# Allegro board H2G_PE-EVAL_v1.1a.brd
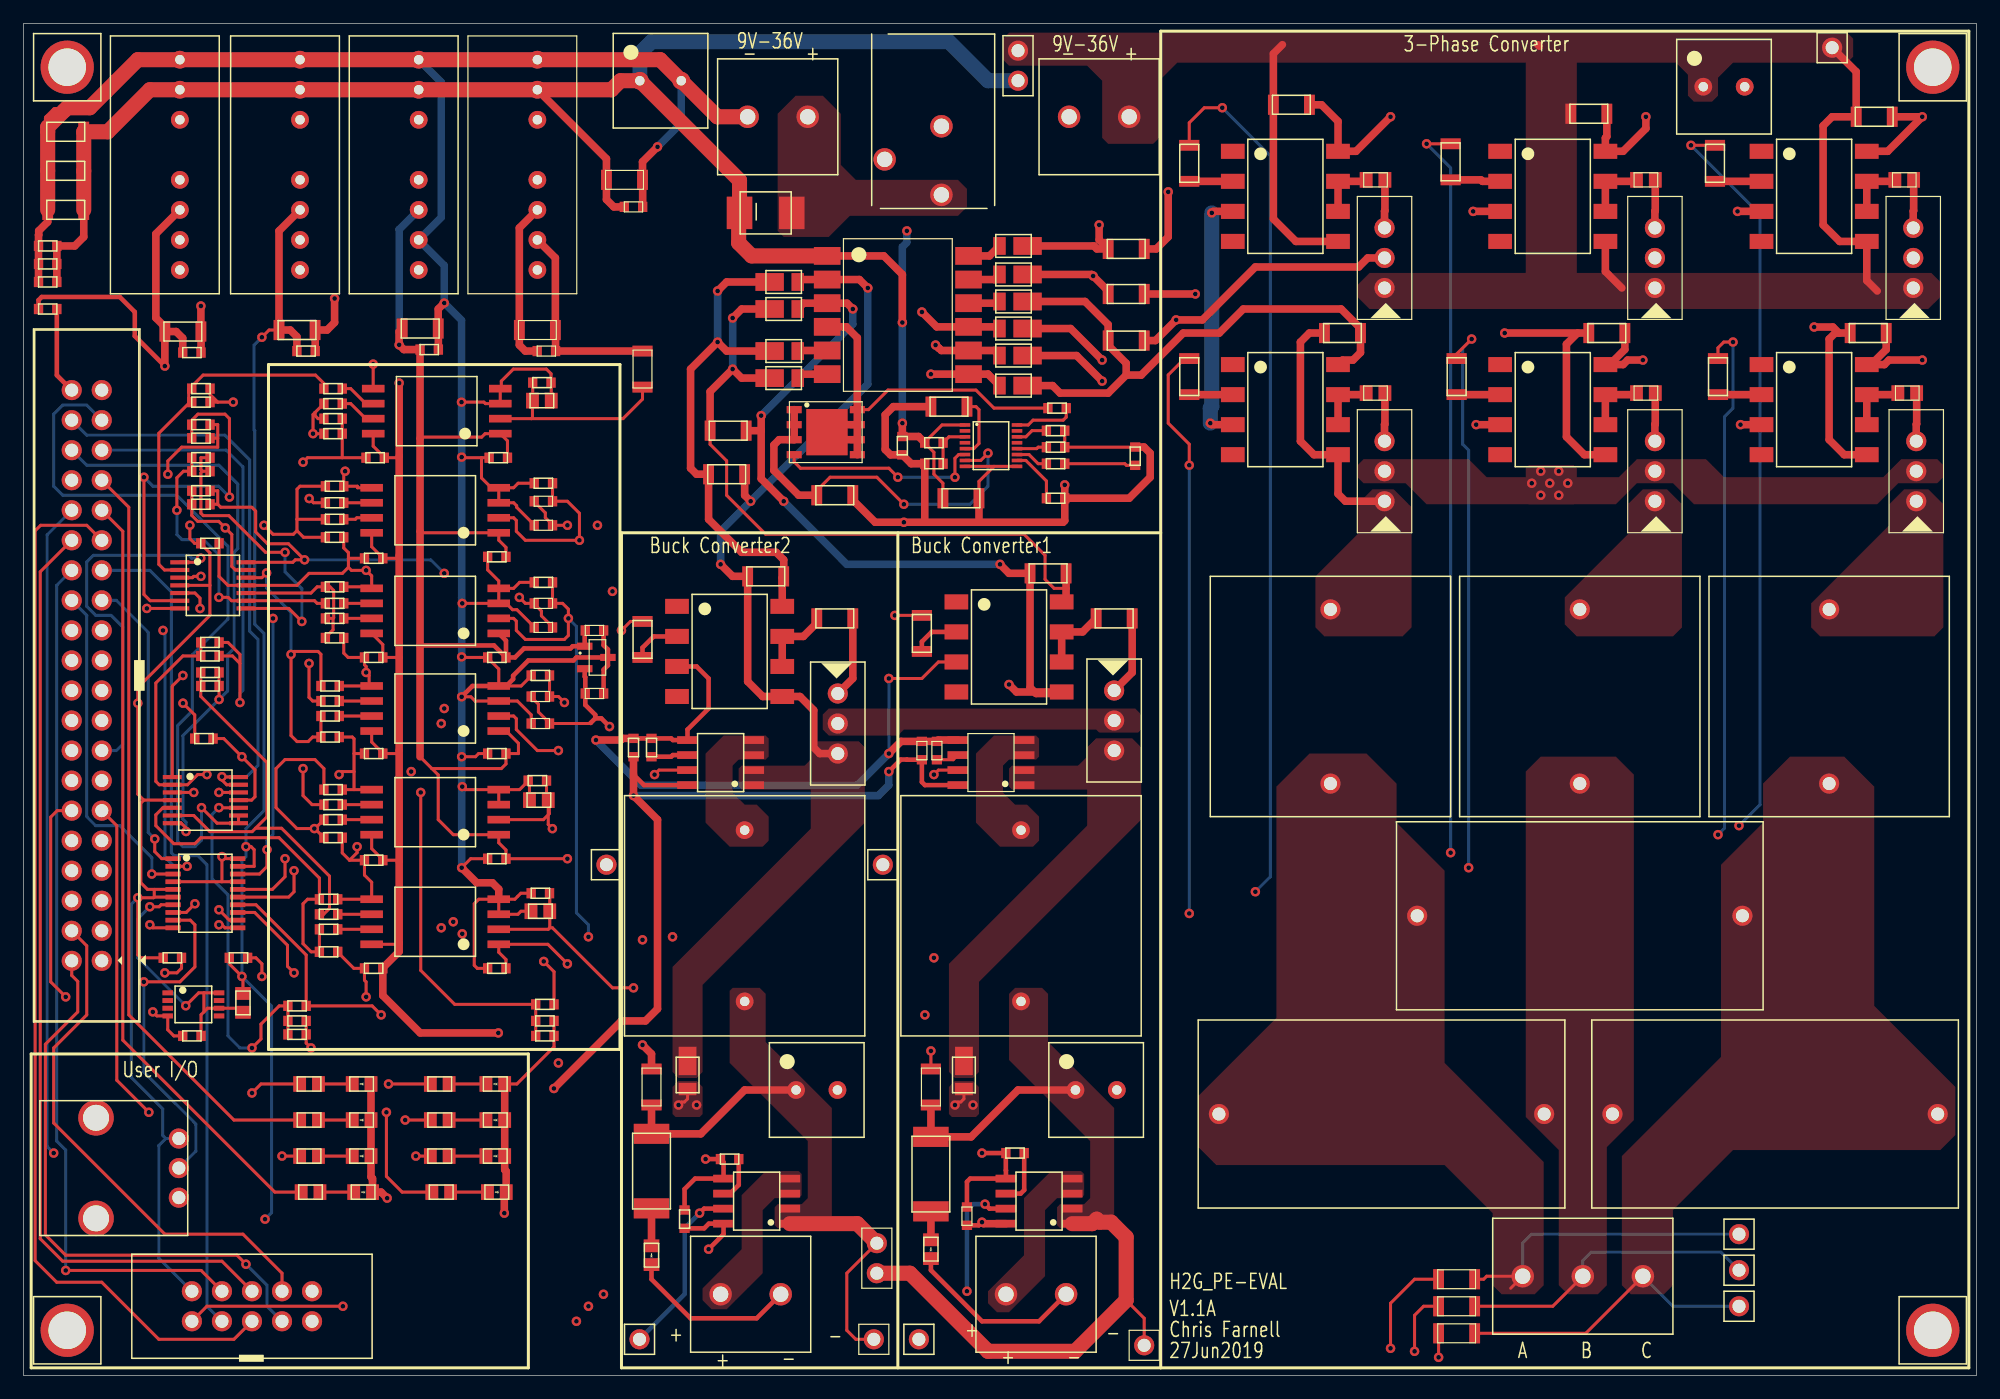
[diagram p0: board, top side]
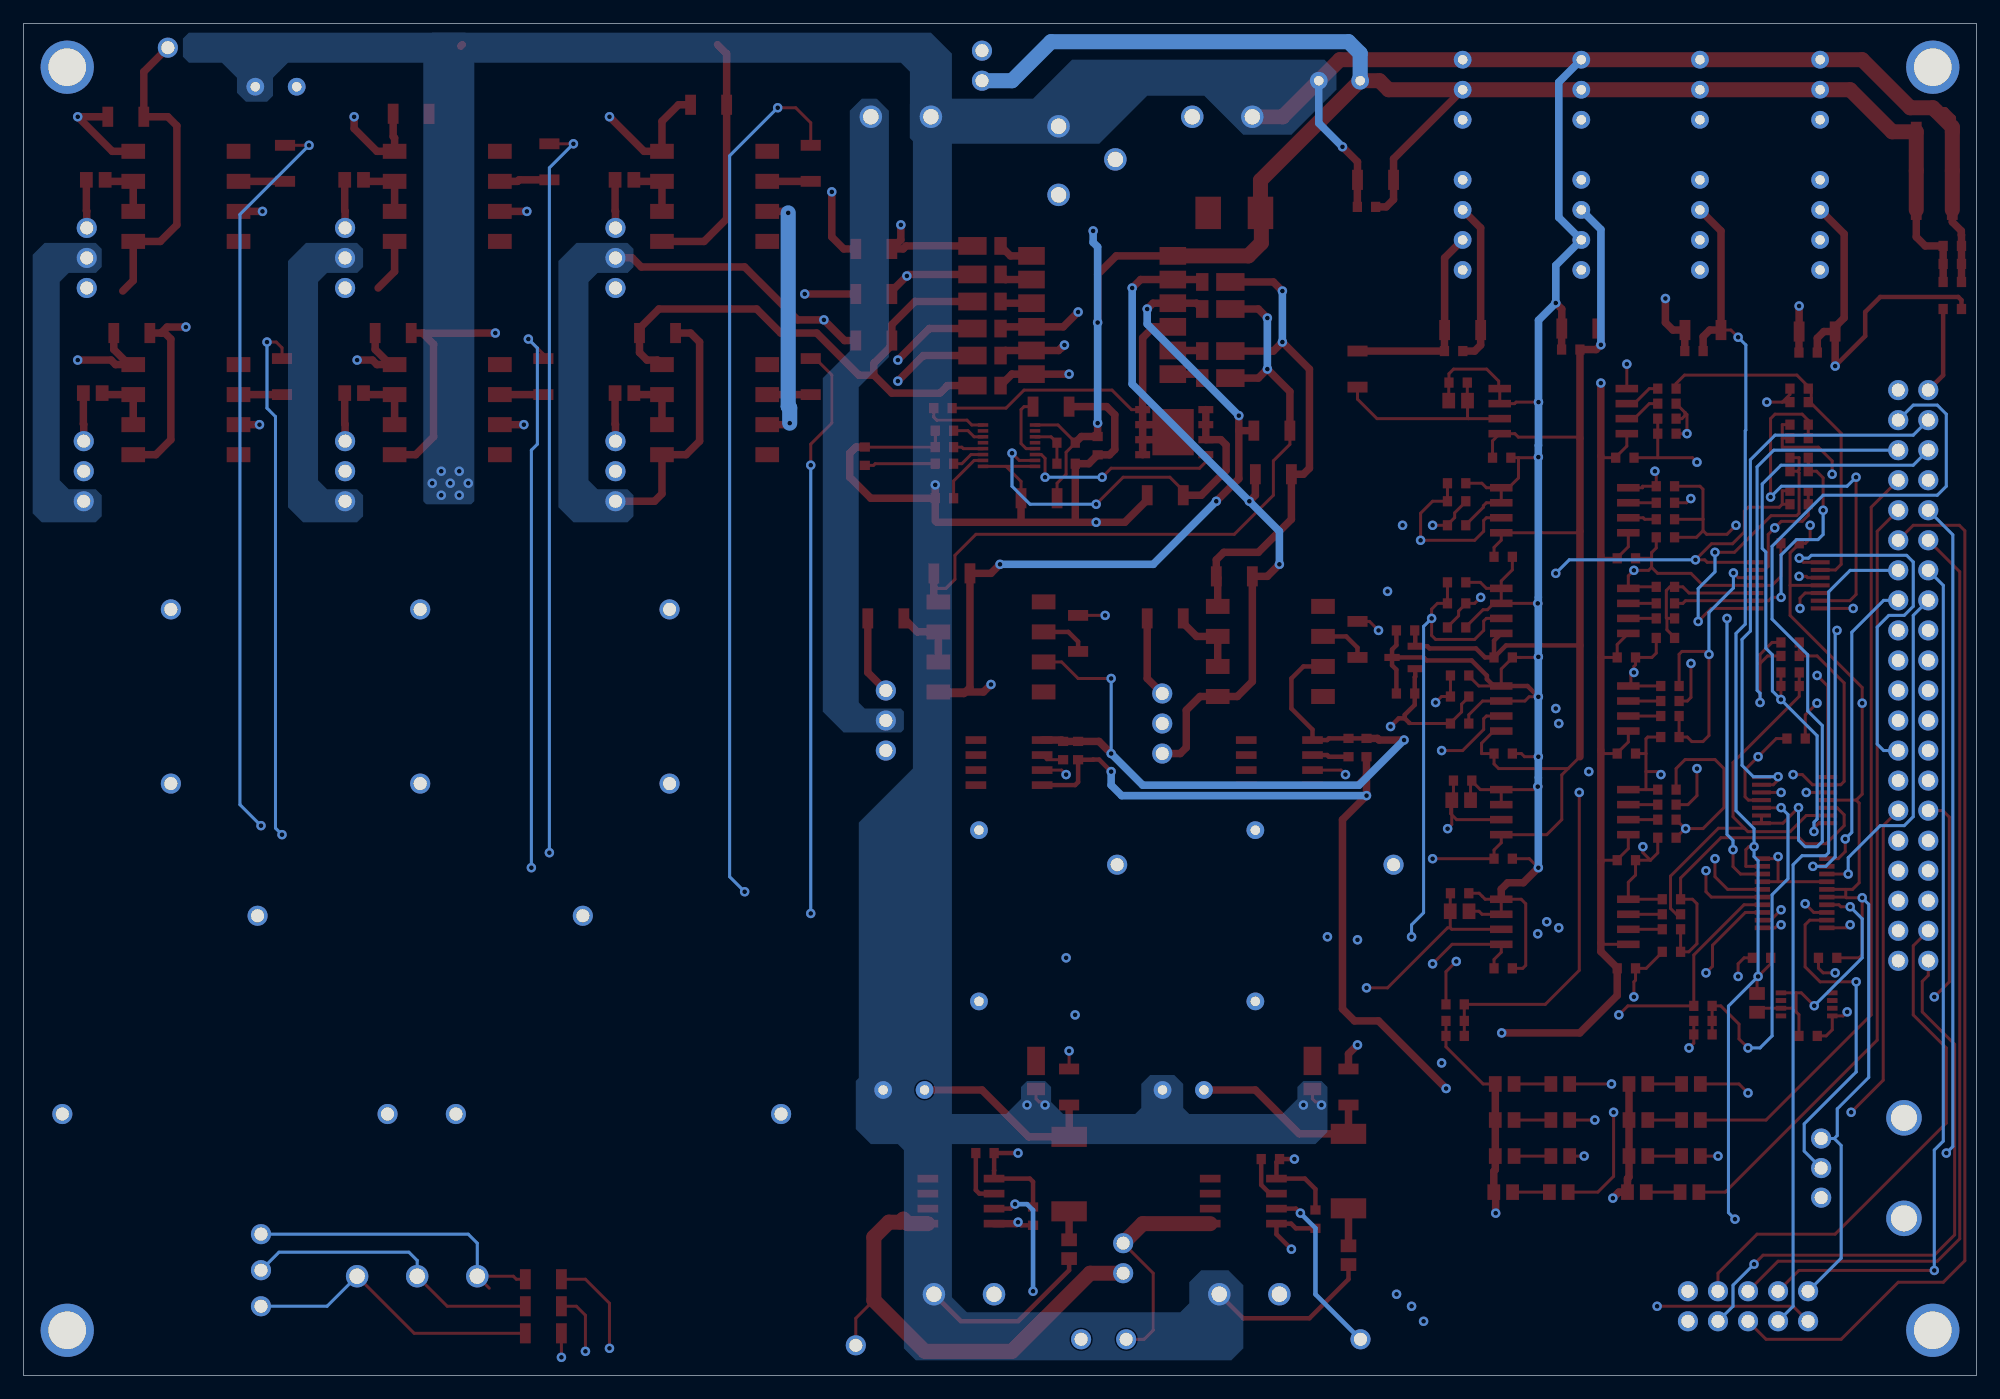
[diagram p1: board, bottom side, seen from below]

Outline 165.1 x 114.3 mm; copper layers: TOP, LAYER2, LAYER3, BOTTOM. Coordinates in mm from the lower left corner of the outline.
Outline path: 0,114.3 165.1,114.3 165.1,0 0,0 0,114.3

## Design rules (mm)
constraint set DEFAULT: min track width 0.254

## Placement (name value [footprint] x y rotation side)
ADC1  AD7928BRUZ  [20-TSSOP]  15.37 40.77 0 top
C1  10uF  [ECQ-E2106KFB]  114.81 22.1 0 top
C2  10uF  [ECQ-E2106KFB]  148.08 22.1 0 top
C3  10uF  [ECQ-E2106KFB]  131.57 38.86 0 top
C4  100uF  [UVZ1H101MPD]  90.68 24.13 0 top
C5  100uF  [UVZ1H101MPD]  53.85 109.47 0 top
C16  10uF  [C_1206]  79.25 74.17 0 top
C17  1uF  [C_0603]  74.29 78.61 270 top
C18  4.7uF  [C_1206]  78.23 81.92 180 top
C19  2.2nF  [C_0603]  87.25 74.17 180 top
C20  4.7nF  [C_0603]  93.98 77.72 270 top
C21  10uF  [C_1206]  93.22 87.5 0 top
C22  10uF  [C_1206]  93.22 91.44 0 top
C23  10uF  [C_1206]  93.22 95.25 0 top
C24  10uF  [C_1206]  59.56 79.88 0 top
C25  10uF  [C_1206]  59.44 76.2 0 top
C26  10uF  [C_1206]  3.56 105.16 180 top
C27  10uF  [C_1206]  3.56 101.85 180 top
C28  10uF  [C_1206]  13.46 88.27 0 top
C29  10uF  [C_1206]  23.11 88.39 0 top
C30  1uF  [C_0603]  2.03 95.5 180 top
C31  1uF  [C_0603]  2.03 93.98 180 top
C32  1uF  [C_0603]  23.88 86.61 0 top
C33  1uF  [C_0603]  14.22 86.49 0 top
C34  100uF  [UVZ1H101MPD]  143.76 108.97 0 top
C35  100uF  [UVZ1H101MPD]  67.06 24.13 0 top
C36  4.7uF  [C_1206]  107.19 107.44 180 top
C37  4.7uF  [C_1206]  132.33 106.68 180 top
C38  4.7uF  [C_1206]  156.46 106.43 180 top
C39  4.7uF  [C_1206]  86.61 67.82 180 top
C40  4.7uF  [C_1206]  111.51 88.14 180 top
C41  4.7uF  [C_1206]  133.86 88.14 180 top
C42  4.7uF  [C_1206]  155.96 88.14 180 top
C43  4.7uF  [C_1206]  62.74 67.56 180 top
C50  1nF  [C_0603]  83.82 18.8 180 top
C51  1nF  [C_0603]  59.69 18.29 180 top
C52  0.1uF  [C_0603]  79.76 13.46 90 top
C53  0.1uF  [C_0603]  55.88 13.21 90 top
C54  10uF  [C_1206]  3.56 98.55 180 top
C55  10uF  [C_1206]  33.53 88.52 0 top
C56  1uF  [C_0603]  2.03 92.46 180 top
C57  1uF  [C_0603]  34.29 86.74 0 top
C58  100pF  [C_0603]  43.81 83.95 0 top
C59  0.1uF  [C_0603]  40.13 77.6 180 top
C60  0.1uF  [C_0603]  29.72 77.6 180 top
C61  100pF  [C_0603]  14.99 82.3 0 top
C62  100pF  [C_0603]  26.16 79.63 180 top
C63  100pF  [C_0603]  43.94 75.44 180 top
C64  0.1uF  [C_0603]  40 69.22 180 top
C65  0.1uF  [C_0603]  29.59 69.09 180 top
C66  100pF  [C_0603]  14.99 79.25 0 top
C67  100pF  [C_0603]  26.29 70.87 180 top
C68  100pF  [C_0603]  43.94 67.06 180 top
C69  0.1uF  [C_0603]  40 60.71 180 top
C70  0.1uF  [C_0603]  29.59 60.71 180 top
C71  100pF  [C_0603]  14.99 76.45 0 top
C72  100pF  [C_0603]  26.29 62.36 180 top
C73  100pF  [C_0603]  43.69 59.18 180 top
C74  0.1uF  [C_0603]  40 52.58 180 top
C75  0.1uF  [C_0603]  29.59 52.58 180 top
C76  100pF  [C_0603]  14.99 73.66 0 top
C77  100pF  [C_0603]  25.91 53.98 180 top
C78  100pF  [C_0603]  43.43 50.29 180 top
C79  0.1uF  [C_0603]  40 43.69 180 top
C80  0.1uF  [C_0603]  29.59 43.56 180 top
C81  100pF  [C_0603]  15.75 60.83 0 top
C82  100pF  [C_0603]  26.16 45.47 180 top
C83  100pF  [C_0603]  43.69 40.77 180 top
C84  0.1uF  [C_0603]  40 34.42 180 top
C85  0.1uF  [C_0603]  29.59 34.42 180 top
C86  100pF  [C_0603]  15.75 58.29 0 top
C87  100pF  [C_0603]  25.78 35.81 180 top
C88  220pF  [C_0603]  23.11 28.83 0 top
C89  220pF  [C_0603]  44.07 28.7 0 top
C96  1uF  [C_0603]  12.57 35.31 0 top
C97  1uF  [C_0603]  18.16 35.31 0 top
C98  1uF  [C_0603]  15.75 70.36 0 top
C99  1uF  [C_0603]  15.24 53.85 0 top
C100  0.1uF  [C_0603]  2.03 90.17 0 top
C102  1uF  [C_0603]  14.22 28.7 0 top
C105  1nF  [C_0603]  53.09 53.09 90 top
C106  0.1uF  [C_0603]  51.56 53.09 90 top
C108  1nF  [C_0603]  77.22 52.83 90 top
C109  0.1uF  [C_0603]  75.95 52.83 90 top
C110  10uF  [C_1206]  43.43 88.39 0 top
C111  1uF  [C_0603]  44.2 86.61 0 top
C112  10uF  [C_1206]  50.8 101.09 0 top
C113  1uF  [C_0603]  51.56 98.81 0 top
C114  0.1uF  [C_0603]  48.26 57.66 0 top
C115  0.1uF  [C_0603]  48.26 62.99 0 top
C116  0.1uF  [C_0603]  43.94 71.88 180 top
C117  0.1uF  [C_0603]  43.94 63.25 180 top
C118  0.1uF  [C_0603]  43.69 55.12 180 top
D1  STPS3150U  [DO-214AA_SMB]  62.74 98.3 0 top
D5  DFLS260-7  [POWERDI-123]  83.69 90.81 180 top
D6  DFLS260-7  [POWERDI-123]  83.69 93.09 180 top
D7  DFLS260-7  [POWERDI-123]  83.69 95.5 180 top
D8  DFLS260-7  [POWERDI-123]  64.26 84.33 0 top
D9  DFLS260-7  [POWERDI-123]  64.26 86.61 0 top
D10  DFLZ18-7  [POWERDI-123]  83.69 83.69 180 top
D11  DFLZ18-7  [POWERDI-123]  83.69 86.23 180 top
D12  DFLZ18-7  [POWERDI-123]  83.69 88.52 180 top
D13  DFLZ18-7  [POWERDI-123]  64.26 90.17 0 top
D14  DFLZ18-7  [POWERDI-123]  64.26 92.46 0 top
D15  DFLS260-7  [POWERDI-123]  79.5 25.4 270 top
D16  DFLS260-7  [POWERDI-123]  56.13 25.4 270 top
D17  LED-R  [LED_0805-RED]  76.71 10.67 90 top
D18  LED-G  [LED_0805-GREEN]  53.09 10.16 90 top
D19  LED-G  [LED_0805-GREEN]  40 15.49 180 top
D20  LED-Y  [LED_0805-YELLOW]  39.88 18.54 180 top
D21  LED-O  [LED_0805-ORANGE]  39.88 21.59 180 top
D22  LED-R  [LED_0805-RED]  39.88 24.64 180 top
D23  LED-G  [LED_0805-GREEN]  28.7 15.49 180 top
D24  LED-Y  [LED_0805-YELLOW]  28.57 18.54 180 top
D25  LED-O  [LED_0805-ORANGE]  28.57 21.59 180 top
D26  LED-R  [LED_0805-RED]  28.57 24.64 180 top
J1  AWHW 40G-0202-T  [40-IDC-M]  5.33 59.18 180 top
J2  -  [1715721]  63.75 106.43 270 top
J3  -  [1715734]  131.83 8.38 90 top
J4  -  [1715721]  85.6 6.86 90 top
J5  -  [1715721]  61.47 6.86 90 top
J6  PJ-102BH  [DC-PWR_JACK]  77.6 106.17 0 top
J7  AWHW 10G-0202-T  [10-IDC-M]  19.3 5.84 90 top
J8  -  [1715721]  90.93 106.43 270 top
JP1  -  [J_1X2]  84.07 110.74 180 top
JP5  -  [J_1X2]  72.14 9.91 180 top
L1  180uH  [PCV-2-184-05L]  110.49 57.4 270 top
L2  180uH  [PCV-2-184-05L]  131.57 57.4 270 top
L3  180uH  [PCV-2-184-05L]  152.65 57.4 270 top
L4  560uH  [PCV-2-564-02L]  84.33 38.86 270 top
L5  560uH  [PCV-2-564-02L]  60.96 38.86 270 top
MECH1  Mech_Hole  [4-40_SCREW]  3.68 110.62 0 top
MECH2  Mech_Hole  [4-40_SCREW]  3.68 3.81 0 top
MECH3  Mech_Hole  [4-40_SCREW]  161.42 110.62 0 top
MECH4  Mech_Hole  [4-40_SCREW]  161.42 3.81 0 top
PM1  EC4SAW-24S33N  [SIP-8]  22.1 102.36 0 top
PM2  EC4SAW-24S05N  [SIP-8]  11.94 102.36 0 top
PM3  EC4SAW-24S05N  [SIP-8]  32.13 102.36 0 top
PM4  EC4SAW-24S15N  [SIP-8]  42.16 102.36 0 top
Q1  STGP15H60DF  [TO-220]  92.2 55.37 0 top
Q2  STGP15H60DF  [TO-220]  68.83 55.12 0 top
Q3  Si7898DP  [SO-8_PP]  67.82 79.76 0 top
R8  825k  [R_0603]  76.96 78.87 0 top
R9  215k  [R_0603]  76.96 77.09 0 top
R10  133k  [R_0603]  87.25 78.49 180 top
R11  10k  [R_0603]  87.25 77.09 180 top
R12  71.5k  [R_0603]  87.38 81.79 180 top
R13  6.04k  [R_0603]  87.25 79.88 0 top
R14  0.01  [R_1206]  68.58 74.42 180 top
R15  2.49k  [R_2512]  76.71 17.02 270 top
R16  2.49k  [R_2512]  53.09 17.27 270 top
R17  120  [R_1206]  98.55 102.49 270 top
R19  120  [R_1206]  120.65 102.62 270 top
R21  120  [R_1206]  143 102.49 270 top
R23  120  [R_1206]  75.95 62.74 270 top
R24  10  [R_1206]  92.2 64.01 0 top
R25  120  [R_1206]  98.55 84.46 270 top
R27  120  [R_1206]  121.16 84.46 270 top
R29  120  [R_1206]  143.26 84.46 270 top
R31  120  [R_1206]  52.32 62.23 270 top
R32  10  [R_1206]  68.58 64.01 0 top
R33  1Meg  [R_1206]  52.32 85.09 270 top
R35  10k  [R_0603]  26.16 82.17 180 top
R36  10k  [R_0603]  26.16 83.44 180 top
R37  10k  [R_0603]  26.16 80.9 180 top
R38  10k  [R_0603]  14.99 83.44 0 top
R39  31.6k  [R_0805]  43.81 82.42 0 top
R40  1Meg  [R_1206]  121.16 8.13 180 top
R41  10k  [R_0603]  26.29 72.39 180 top
R42  10k  [R_0603]  26.29 73.79 180 top
R43  10k  [R_0603]  26.29 75.18 180 top
R44  10k  [R_0603]  14.99 80.39 0 top
R45  13.7k  [R_0603]  43.94 73.91 180 top
R46  1Meg  [R_1206]  121.16 5.84 180 top
R47  10k  [R_0603]  26.29 64.01 180 top
R48  10k  [R_0603]  26.29 65.28 180 top
R49  10k  [R_0603]  26.29 66.68 180 top
R50  10k  [R_0603]  14.99 77.6 0 top
R51  13.7k  [R_0603]  43.94 65.28 180 top
R52  1Meg  [R_1206]  121.16 3.56 180 top
R53  10k  [R_0603]  25.91 55.75 180 top
R54  10k  [R_0603]  25.91 57.02 180 top
R55  10k  [R_0603]  25.91 58.29 180 top
R56  10k  [R_0603]  14.99 74.8 0 top
R57  13.7k  [R_0603]  43.69 57.4 180 top
R58  1Meg  [R_1206]  76.71 24.38 90 top
R59  10k  [R_0603]  26.16 46.99 180 top
R60  10k  [R_0603]  26.16 48.26 180 top
R61  10k  [R_0603]  26.16 49.53 180 top
R62  10k  [R_0603]  15.75 61.98 0 top
R63  31.6k  [R_0805]  43.56 48.64 180 top
R64  1Meg  [R_1206]  53.09 24.38 90 top
R65  10k  [R_0603]  25.78 37.72 180 top
R66  10k  [R_0603]  25.78 38.99 180 top
R67  10k  [R_0603]  25.78 40.26 180 top
R68  10k  [R_0603]  15.75 59.44 0 top
R69  31.6k  [R_0805]  43.69 39.24 180 top
R70  10k  [R_0603]  23.11 31.24 180 top
R71  15k  [R_0603]  23.11 29.97 0 top
R72  10k  [R_0603]  44.07 31.37 180 top
R73  15k  [R_0603]  44.07 29.97 0 top
R74  PTV09A-4020F-B103  [9MM_POT]  7.62 17.53 180 top
R75  1k  [R_0805]  18.54 31.5 270 top
R80  220  [R_0805]  35.31 15.49 0 top
R81  220  [R_0805]  35.18 18.54 0 top
R82  220  [R_0805]  35.18 21.59 0 top
R83  220  [R_0805]  35.18 24.64 0 top
R84  220  [R_0805]  24.26 15.49 0 top
R85  220  [R_0805]  24.13 18.54 0 top
R86  220  [R_0805]  24.13 21.59 0 top
R87  220  [R_0805]  24.13 24.64 0 top
R88  1k  [R_0805]  114.3 101.09 0 top
R89  1k  [R_0805]  114.3 83.06 0 top
R90  1k  [R_0805]  137.16 101.09 0 top
R91  1k  [R_0805]  137.16 83.06 0 top
R92  1k  [R_0805]  159 101.09 0 top
R93  1k  [R_0805]  159.26 83.06 0 top
SCR1  SJ6020LTP  [TO-220]  115.06 94.49 180 top
SCR2  SJ6020LTP  [TO-220]  115.06 76.45 180 top
SCR3  SJ6020LTP  [TO-220]  137.92 94.49 180 top
SCR4  SJ6020LTP  [TO-220]  137.92 76.45 180 top
SCR5  SJ6020LTP  [TO-220]  159.77 94.49 180 top
SCR6  SJ6020LTP  [TO-220]  160.02 76.45 180 top
TP1  TP-Y  [TP-YELLOW]  75.69 3.05 0 top
TP2  TP-Y  [TP-YELLOW]  52.07 3.05 0 top
TP3  TP-Y  [TP-YELLOW]  72.64 43.18 0 top
TP4  TP-Y  [TP-YELLOW]  49.28 43.18 0 top
TP5  TP-Y  [TP-YELLOW]  145.03 11.94 0 top
TP6  TP-Y  [TP-YELLOW]  145.03 8.89 0 top
TP7  TP-Y  [TP-YELLOW]  145.03 5.84 270 top
TP8  TP-Y  [TP-YELLOW]  152.91 112.27 270 top
TP9  TP-Y  [TP-YELLOW]  94.74 2.54 0 top
TP10  TP-Y  [TP-YELLOW]  71.88 3.05 0 top
TX1  VP1-0102-R  [TX-VP1]  73.91 89.66 0 top
U3  LT3748EMS#PBF-ND  [16-MSOP]  81.79 78.61 0 top
U6  ACS714LLCTR-05B-T  [8-SOIC]  85.85 14.73 180 top
U7  ACS714LLCTR-05B-T  [8-SOIC]  61.98 14.73 180 top
U8  HCPL-3120-300E  [8-DIP_GW]  106.68 99.69 0 top
U9  HCPL-3120-300E  [8-DIP_GW]  129.29 99.69 0 top
U10  HCPL-3120-300E  [8-DIP_GW]  151.38 99.69 0 top
U11  HCPL-3120-300E  [8-DIP_GW]  83.31 61.59 0 top
U12  HCPL-3120-300E  [8-DIP_GW]  106.68 81.66 0 top
U13  HCPL-3120-300E  [8-DIP_GW]  129.29 81.66 0 top
U14  HCPL-3120-300E  [8-DIP_GW]  151.38 81.66 0 top
U15  HCPL-3120-300E  [8-DIP_GW]  59.69 61.21 0 top
U16  OPA4322AIPWR  [OPA4332_14-TSSOP]  16 66.8 0 top
U17  OPA4322AIPWR  [OPA4332_14-TSSOP]  15.37 48.64 0 top
U20  ACPL-C87B  [ACPL-C87X]  34.93 81.53 180 top
U21  ACPL-C87B  [ACPL-C87X]  34.8 73.15 180 top
U22  ACPL-C87B  [ACPL-C87X]  34.8 64.64 180 top
U23  ACPL-C87B  [ACPL-C87X]  34.8 56.39 180 top
U24  ACPL-C87B  [ACPL-C87X]  34.8 47.62 180 top
U25  ACPL-C87B  [ACPL-C87X]  34.8 38.35 180 top
U27  LT1009CZ  [8-MSOP]  14.35 31.37 0 top
U30  ACS714LLCTR-05B-T  [8-SOIC]  58.93 51.82 180 top
U31  ACS714LLCTR-05B-T  [8-SOIC]  81.79 51.82 180 top
U32  ISL21080  [SOT_23-3]  48.51 60.71 0 top

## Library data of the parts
ADC1 = AD7928BRUZ
C1-C3 C16-C33 C36-C43 C50-C89 C96-C100 C102 C105 C106 C108-C118 = CAP NP
C4 C5 C34 C35 = CAP P
D1 D5-D9 D15 D16 = D-Schottky
D10-D14 = D-Zener
D17-D26 = LED
J1 = Header_2x20
J2 J4 J5 J8 = Connector-2
J3 = Connector-3
J6 = DC-Jack_3
J7 = Header_2x5
JP1 JP5 = JP2
L1-L5 = Ind
MECH1-MECH4 = Mech_Hole
PM1-PM4 = EC4SA
Q1 Q2 = IGBT_TO220
Q3 = N-FET_Si7898DP
R8-R17 R19 R21 R23-R25 R27 R29 R31-R33 R35-R73 R75 R80-R93 = R-Standard
R74 = R-POT
SCR1-SCR6 = SJ6020LTP
TP1-TP10 = TP
TX1 = TX_VP1-0102-R
U3 = LT3748EMS#PBF-ND
U6 U7 U30 U31 = ACS714
U8-U15 = HCPL-3120
U16 U17 = OPA4322AIPWR
U20-U25 = ACPL-C87B
U27 = LT1009CZ
U32 = ISL21080

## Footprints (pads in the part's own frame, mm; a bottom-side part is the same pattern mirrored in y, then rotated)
4-40_SCREW
  round 4.5 hole 3.175: 1(0,0)
8-DIP_GW
  rect 2x1.27 smd: 1(-4.45,3.81) 2(-4.45,1.27) 3(-4.45,-1.27) 4(-4.45,-3.81) 5(4.45,-3.81) 6(4.45,-1.27) 7(4.45,1.27) 8(4.45,3.81)
8-MSOP
  rect 0.889x0.42 smd: 1(-2.17,0.975) 2(-2.17,0.325) 3(-2.17,-0.325) 4(-2.17,-0.975) 5(2.17,-0.975) 6(2.17,-0.325) 7(2.17,0.325) 8(2.17,0.975)
8-SOIC
  rect 1.75x0.65 smd: 1(-2.8,1.905) 2(-2.8,0.635) 3(-2.8,-0.635) 4(-2.8,-1.905) 5(2.8,-1.905) 6(2.8,-0.635) 7(2.8,0.635) 8(2.8,1.905)
9MM_POT
  round 3 hole 2.2: (1.5,4.25) (1.5,-4.25)
  round 1.7 hole 1.1: 1(-5.5,2.5) 2(-5.5,0) 3(-5.5,-2.5)
10-IDC-M
  round 1.7 hole 1.1: 1(-1.27,5.08) 2(1.27,5.08) 3(-1.27,2.54) 4(1.27,2.54) 5(-1.27,0) 6(1.27,0) 7(-1.27,-2.54) 8(1.27,-2.54) 9(-1.27,-5.08) 10(1.27,-5.08)
16-MSOP
  rect 0.89x0.305 smd: 1(-2.2,1.75) 2(-2.2,1.25) 3(-2.2,0.75) 4(-2.2,0.25) 5(-2.2,-0.25) 6(-2.2,-0.75) 7(-2.2,-1.25) 8(-2.2,-1.75) 9(2.2,-1.75) 10(2.2,-1.25) 11(2.2,-0.75) 12(2.2,-0.25) 13(2.2,0.25) 14(2.2,0.75) 15(2.2,1.25) 16(2.2,1.75)
20-TSSOP
  rect 1.3x0.4 smd: 1(-2.725,2.925) 2(-2.725,2.275) 3(-2.725,1.625) 4(-2.725,0.975) 5(-2.725,0.325) 6(-2.725,-0.325) 7(-2.725,-0.975) 8(-2.725,-1.625) 9(-2.725,-2.275) 10(-2.725,-2.925) 11(2.725,-2.925) 12(2.725,-2.275) 13(2.725,-1.625) 14(2.725,-0.975) 15(2.725,-0.325) 16(2.725,0.325) 17(2.725,0.975) 18(2.725,1.625) 19(2.725,2.275) 20(2.725,2.925)
40-IDC-M
  round 1.7 hole 1.1: 1(-1.27,24.13) 2(1.27,24.13) 3(-1.27,21.59) 4(1.27,21.59) 5(-1.27,19.05) 6(1.27,19.05) 7(-1.27,16.51) 8(1.27,16.51) 9(-1.27,13.97) 10(1.27,13.97) 11(-1.27,11.43) 12(1.27,11.43) 13(-1.27,8.89) 14(1.27,8.89) 15(-1.27,6.35) 16(1.27,6.35) 17(-1.27,3.81) 18(1.27,3.81) 19(-1.27,1.27) 20(1.27,1.27) 21(-1.27,-1.27) 22(1.27,-1.27) 23(-1.27,-3.81) 24(1.27,-3.81) 25(-1.27,-6.35) 26(1.27,-6.35) 27(-1.27,-8.89) 28(1.27,-8.89) 29(-1.27,-11.43) 30(1.27,-11.43) 31(-1.27,-13.97) 32(1.27,-13.97) 33(-1.27,-16.51) 34(1.27,-16.51) 35(-1.27,-19.05) 36(1.27,-19.05) 37(-1.27,-21.59) 38(1.27,-21.59) 39(-1.27,-24.13) 40(1.27,-24.13)
1715721
  round 1.9 hole 1.3: 1(0,2.54) 2(0,-2.54)
1715734
  round 1.9 hole 1.3: 1(0,5.08) 2(0,0) 3(0,-5.08)
ACPL-C87X
  rect 1.905x0.64 smd: 1(-5.372,1.905) 2(-5.372,0.635) 3(-5.372,-0.635) 4(-5.372,-1.905) 5(5.372,-1.905) 6(5.372,-0.635) 7(5.372,0.635) 8(5.372,1.905)
C_0603
  rect 0.787x0.864 smd: 1(-0.775,0) 2(0.775,0)
C_1206
  rect 0.914x1.702 smd: 1(-1.524,0) 2(1.524,0)
DC-PWR_JACK
  round 1.9 hole 1.3: 1(0,-6.35) 2(0,-0.55) 3(-4.8,-3.35)
DO-214AA_SMB
  rect 2.159x2.743 smd: 1(-2.21,0) 2(2.21,0)
ECQ-E2106KFB
  round 1.7 hole 1.1: 1(-13.75,0) 2(13.75,0)
J_1X2
  round 1.7 hole 1.1: 1(0,1.27) 2(0,-1.27)
LED_0805-GREEN
  rect 1.08x1.321 smd: 1(-0.794,0) 2(0.794,0)
LED_0805-ORANGE
  rect 1.08x1.321 smd: 1(-0.794,0) 2(0.794,0)
LED_0805-RED
  rect 1.08x1.321 smd: 1(-0.794,0) 2(0.794,0)
LED_0805-YELLOW
  rect 1.08x1.321 smd: 1(-0.794,0) 2(0.794,0)
OPA4332_14-TSSOP
  rect 1.6x0.35 smd: 1(-2.8,1.95) 2(-2.8,1.3) 3(-2.8,0.65) 4(-2.8,0) 5(-2.8,-0.65) 6(-2.8,-1.3) 7(-2.8,-1.95) 8(2.8,-1.95) 9(2.8,-1.3) 10(2.8,-0.65) 11(2.8,0) 12(2.8,0.65) 13(2.8,1.3) 14(2.8,1.95)
PCV-2-184-05L
  round 1.7 hole 1.1: 1(-7.365,0) 2(7.365,0)
PCV-2-564-02L
  round 1.5 hole 0.8: 1(-7.24,0) 2(7.24,0)
POWERDI-123
  rect 2.4x1.5 smd: 1(-1.188,0)
  rect 1.05x1.5 smd: 2(1.188,0)
R_0603
  rect 0.787x0.864 smd: 1(-0.775,0) 2(0.775,0)
R_0805
  rect 1.08x1.321 smd: 1(-0.794,0) 2(0.794,0)
R_1206
  rect 0.914x1.702 smd: 1(-1.524,0) 2(1.524,0)
R_2512
  rect 1.7x3 smd: 1(-3.15,0) 2(3.15,0)
SIP-8
  round 1.5 hole 0.8: 1(1.27,8.89) 2(1.27,6.35) 3(1.27,3.81) 5(1.27,-1.27) 6(1.27,-3.81) 7(1.27,-6.35) 8(1.27,-8.89)
SO-8_PP
  rect 1.27x0.61 smd: 1(-2.67,1.905) 2(-2.67,0.635) 3(-2.67,-0.635) 4(-2.67,-1.905) 5(2.67,-1.905) 6(2.67,-0.635) 7(2.67,0.635) 8(2.67,1.905)
  rect 3.5x3.91 smd: 9(0.1,0)
SOT_23-3
  rect 1.3x0.6 smd: 1(-1.075,0.95) 2(-1.075,-0.95) 3(0.889,0)
TO-220
  round 1.7 hole 1.1: 1(0,2.54) 2(0,0) 3(0,-2.54)
TP-YELLOW
  round 1.7 hole 1.1: 1(0,0)
TX-VP1
  rect 2.25x1.5 smd: 1(-5.975,5) 2(-5.975,3) 3(-5.975,1) 4(-5.975,-1) 5(-5.975,-3) 6(-5.975,-5) 7(5.975,-5) 8(5.975,-3) 9(5.975,-1) 10(5.975,1) 11(5.975,3) 12(5.975,5)
UVZ1H101MPD
  round 1.5 hole 0.8: 1(-1.75,0) 2(1.75,0)

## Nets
0V9: C114.1 C116.1 C117.1 C118.1 R45.2 R51.2 R57.2 U32.2(V_OUT)
3V3_ISO: ADC1.19 C29.1 C32.1 C97.1 J7.1 PM1.6 R75.1
5V: C55.1 C57.1 C59.1 C64.1 C69.1 C74.1 C79.1 C84.1 C115.1 PM3.6 U20.1 U21.1 U22.1 U23.1 U24.1 U25.1 U32.1
5V_ISO: ADC1.5 ADC1.6 C28.1 C33.1 C52.1 C53.1 C60.1 C65.1 C70.1 C75.1 C80.1 C85.1 C96.1 C98.1 C99.1 C100.1 C106.1 C109.1 J7.2 PM2.6 R74.3 U6.8 U7.8 U16.4 U17.4 U20.8 U21.8 U22.8 U23.8 U24.8 U25.8 U30.8 U31.8
18V_GU: C36.1 C37.1 C38.1 C110.1 C111.1 PM4.6 U8.8 U9.8 U10.8
18V_IGBT1: C24.1 C39.1 D8.1 D13.1 U11.8
18V_IGBT2: C25.1 C43.1 D9.1 D14.1 U15.8
18V_SCR2: C21.1 C40.1 D5.1 D10.1 U12.8
18V_SCR4: C22.1 C41.1 D6.1 D11.1 U13.8
18V_SCR6: C23.1 C42.1 D7.1 D12.1 U14.8
GND: C4.2 C5.2 C16.2 C17.2 C18.2 C19.1 C20.1 C26.2 C27.2 C30.2 C31.2 C34.2 C35.2 C54.2 C55.2 C56.2 C57.2 C58.2 C59.2 C63.2 C64.2 C68.2 C69.2 C73.2 C74.2 C78.2 C79.2 C83.2 C84.2 C112.2 C113.2 C114.2 C115.2 C116.2 C117.2 C118.2 D15.2 D16.2 D17.1(CATHODE) D18.1(CATHODE) J2.2(P2) J4.2(P2) J5.2(P2) J6.2 J8.2(P2) PM1.1 PM2.1 PM3.1 PM3.7 PM4.1 R9.1 R10.1 R13.2 R14.1 R39.2 R63.2 R69.2 SCR2.2 SCR4.2 SCR6.2 U3.8 U3.9 U20.3 U20.4 U21.3 U21.4 U22.3 U22.4 U23.3 U23.4 U24.3 U24.4 U25.3 U25.4 U32.3
GND_SIGNAL: ADC1.4 ADC1.8 ADC1.17 ADC1.20 C28.2 C29.2 C32.2 C33.2 C50.2 C51.2 C52.2 C53.2 C60.2 C62.1 C65.2 C67.1 C70.2 C72.1 C75.2 C77.1 C80.2 C82.1 C85.2 C87.1 C88.2 C89.2 C96.2 C97.2 C98.2 C99.2 C100.2 C102.1 C105.2 C106.2 C108.2 C109.2 D19.1(CATHODE) D20.1(CATHODE) D21.1(CATHODE) D22.1(CATHODE) D23.1(CATHODE) D24.1(CATHODE) D25.1(CATHODE) D26.1(CATHODE) J1.20 J1.40 J7.9 J7.10 PM1.7 PM2.7 R37.1 R43.1 R49.1 R55.1 R61.1 R67.1 R71.2 R73.2 R74.1 U6.5 U7.5 U8.3 U9.3 U10.3 U11.3 U12.3 U13.3 U14.3 U15.3 U16.11(V-) U17.11(V-) U20.5 U21.5 U22.5 U23.5 U24.5 U25.5 U27.4 U30.5 U31.5
VIN: C5.1 C16.1 C17.1 C26.1 C27.1 C30.1 C31.1 C54.1 C56.1 C112.1 C113.1 D1.1 JP1.1 PM1.2 PM2.2 PM3.2 PM4.2 R8.1 TX1.1 U3.1(VIN)
ADC-VPOT-3V: J1.38 U17.13 U17.14
ADC_DC-LINK: C61.2 J1.15 R38.2 U16.1
ADC_I_BUCK-1_3V: J1.37 U17.8 U17.9
ADC_V_BUCK-1: C81.2 J1.35 R62.2 U17.1
ADC_V_BUCK-2: C86.2 J1.36 R68.2 U17.7
ADC_VA: ADC1.12 C66.2 J1.16 R44.2 U16.7
ADC_VB: ADC1.11 C71.2 J1.17 R50.2 U16.8
ADC_VC: ADC1.10 C76.2 J1.18 R56.2 U16.14
DC-LINK: C34.1 C36.2 C37.2 C38.2 C110.2 C111.2 J8.1 JP1.2 PM4.7 Q1.2 Q2.2 R33.1 SCR1.1(K) SCR3.1(K) SCR5.1(K) TP8.1 U8.5 U9.5 U10.5
DSP_G1: J1.1 R23.1
DSP_G2: J1.2 J7.7
DSP_G3: J1.3 R31.1
DSP_G4: J1.4 J7.8
DSP_G5: J1.5 R17.1
DSP_G6: J1.6 R25.1
DSP_G7: J1.7 R19.1
DSP_G8: J1.8 R27.1
DSP_G9: J1.9 R21.1
DSP_G10: J1.10 R29.1
GPIO-20: J1.27 J7.3
GPIO-21: J1.28 J7.4
GPIO-22: J1.29 J7.5
GPIO-23: J1.30 J7.6
I_BUCK-1: ADC1.14 R70.1 TP1.1 U6.7(VOUT)
I_BUCK-2: ADC1.13 TP2.1 U7.7(VOUT)
I_L4: ADC1.16 TP3.1 U31.7(VOUT)
I_L5: ADC1.15 TP4.1 U30.7(VOUT)
IGBT_G1: Q1.1(G) R24.2
IGBT_G2: Q2.1(G) R32.2
IGBT_S1: C24.2 C39.2 D13.2 D15.1 Q1.3 TX1.3 U11.5 U31.1 U31.2
IGBT_S2: C25.2 C43.2 D14.2 D16.1 Q2.3 TX1.2 U15.5 U30.1 U30.2
LED1: J1.11 R80.1
LED2: J1.12 R81.1
LED3: J1.13 R82.1
LED4: J1.14 R83.1
LED5: J1.31 R84.1
LED6: J1.32 R85.1
LED7: J1.33 R86.1
LED8: J1.34 R87.1
SCR_G1: R88.2 SCR1.3
SCR_G2: R89.2 SCR2.3
SCR_G3: R90.2 SCR3.3
SCR_G4: R91.2 SCR4.3
SCR_G5: R92.2 SCR5.3
SCR_G6: R93.2 SCR6.3
SPI_CS: ADC1.3 J1.26
SPI_DIN: ADC1.2 J1.23
SPI_DOUT: ADC1.18 J1.24
SPI_SCLK: ADC1.1 J1.25
SW_1: J1.21
SW_2: J1.22
V_BUCK-1: C4.1 JP5.1 L4.2 R15.1 R58.1 TP9.1 U6.1 U6.2
V_BUCK-2: C35.1 JP5.2 L5.2 R16.1 R64.1 TP10.1 U7.1 U7.2
VA: C1.1 C3.1 J3.1 L1.2 R40.1 TP5.1
VB: C1.2 C2.1 J3.2 L2.2 R46.1 TP6.1
VC: C2.2 C3.2 J3.3(P3) L3.2 R52.1 TP7.1
VMID1: C21.2 C40.2 D10.2 L1.1 SCR1.2 SCR2.1(K) TX1.7 U12.5
VMID2: C22.2 C41.2 D11.2 L2.1 SCR3.2 SCR4.1(K) TX1.8 U13.5
VMID3: C23.2 C42.2 D12.2 L3.1 SCR5.2 SCR6.1(K) TX1.9 U14.5
VPOT: ADC1.9(VIN7) R72.1 R74.2(WIPER)
N07970: R8.2 R9.2 U3.3
N08403: C18.1 U3.5
N08410: R10.2 U3.12
N08443: C19.2 U3.10
N08455: R11.2 U3.11
N08467: C20.2 R11.1
N09759: Q3.1 Q3.2 Q3.3(S3) R14.2 U3.7
N09873: Q3.5 Q3.6 Q3.7 Q3.8 Q3.9 R12.2 TX1.4
N10901: Q3.4 U3.6
N10913: R12.1 U3.16
N10917: R13.1 U3.14
N11491: D7.2 TX1.12
N11495: D6.2 TX1.11
N11499: D5.2 TX1.10
N11507: D8.2 TX1.6
N11532: D9.2 TX1.5
N38522: D17.2 R15.2
N38634: D18.2 R16.2
N38702: J4.1 U6.3 U6.4
N38762: J5.1 U7.3 U7.4
N41110: C50.1 U6.6
N41352: C51.1 U7.6
N42617: D1.2 J2.1 J6.1
N48243: C62.2 R35.2 R37.2 U16.3
N48256: R35.1 U20.7
N48260: R36.1 U20.6(VOUT-)
N48264: C61.1 R36.2 R38.1 U16.2
N48807: C58.1 R33.2 R39.1 U20.2
N51115: C67.2 R41.2 R43.2 U16.5
N51119: R41.1 U21.7
N51123: R42.1 U21.6(VOUT-)
N51127: C66.1 R42.2 R44.1 U16.6
N51293: C63.1 R40.2 R45.1 U21.2
N52251: C72.2 R47.2 R49.2 U16.10
N52255: R47.1 U22.7
N52259: R48.1 U22.6(VOUT-)
N52263: C71.1 R48.2 R50.1 U16.9
N52425: C68.1 R46.2 R51.1 U22.2
N53429: C77.2 R53.2 R55.2 U16.12
N53433: R53.1 U23.7
N53437: R54.1 U23.6(VOUT-)
N53441: C76.1 R54.2 R56.1 U16.13
N53579: C73.1 R52.2 R57.1 U23.2
N54653: C82.2 R59.2 R61.2 U17.3
N54657: R59.1 U24.7
N54661: R60.1 U24.6(VOUT-)
N54665: C81.1 R60.2 R62.1 U17.2
N54807: C78.1 R58.2 R63.1 U24.2
N56809: C87.2 R65.2 R67.2 U17.5
N56813: R65.1 U25.7
N56817: R66.1 U25.6(VOUT-)
N56821: C86.1 R66.2 R68.1 U17.6
N56959: C83.1 R64.2 R69.1 U25.2
N58569: C88.1 R70.2 R71.1 U17.10
N59411: C89.1 R72.2 R73.1 U17.12
N71004: ADC1.7 C102.2 R75.2 U27.6(V+.) U27.8
N126025: D19.2 R80.2
N126027: D25.2 R86.2
N126029: D24.2 R85.2
N126031: D23.2 R84.2
N126033: D22.2 R83.2
N126035: D26.2 R87.2
N126037: D21.2 R82.2
N126039: D20.2 R81.2
N179536: R17.2 U8.2
N179562: R88.1 U8.6 U8.7(V_OUT.)
N179712: R19.2 U9.2
N179754: R90.1 U9.6 U9.7(V_OUT.)
N179920: R21.2 U10.2
N179946: R92.1 U10.6 U10.7(V_OUT.)
N180096: R23.2 U11.2
N180138: R24.1 U11.6 U11.7(V_OUT.)
N180288: R25.2 U12.2
N180330: R89.1 U12.6 U12.7(V_OUT.)
N180476: R27.2 U13.2
N180502: R91.1 U13.6 U13.7(V_OUT.)
N180632: R29.2 U14.2
N180674: R93.1 U14.6 U14.7(V_OUT.)
N180804: R31.2 U15.2
N180846: R32.1 U15.6 U15.7(V_OUT.)
N223775: C105.1 U30.6
N223929: L5.1 U30.3 U30.4
N248745: C108.1 U31.6
N249090: L4.1 U31.3 U31.4

Pads without a net: J1 19 39; J6 3; MECH1 1; MECH2 1; MECH3 1; MECH4 1; PM1 3 5 8; PM2 3 5 8; PM3 3 5 8; PM4 3 5 8; U3 2 4 13 15; U8 1 4; U9 1 4; U10 1 4; U11 1 4; U12 1 4; U13 1 4; U14 1 4; U15 1 4; U27 1 2 3 5 7

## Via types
v1: diameter 0.8, hole 0.4, TOP to BOTTOM, 222 vias

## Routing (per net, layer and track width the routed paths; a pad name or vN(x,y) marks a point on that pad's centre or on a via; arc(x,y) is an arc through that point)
0V9: length 51
  TOP w0.254: C117.1 44.72,63.28 43.78,64.23 43.78,64.63 43.17,65.24 R51.2 42.42,65.28 v1(41.91,65.79) ; 47.95,55.17 47.89,55.12 C118.1 44.46,55.16 43.52,56.1 43.52,56.76 42.91,57.37 R57.2 ; R45.2 43.17,73.88 44.11,72.93 44.11,72.53 44.72,71.92 C116.1 v1(45.97,71.88)
  TOP w0.381: 48.33,55.56 47.95,55.17 ; 48.33,55.56 48.84,55.56 v1(49.53,54.86) ; 48.33,55.56 48.33,55.85 47.49,56.7 C114.1 47.49,59.04 47.44,59.09 U32.2
  LAYER2 w0.254: v1(45.97,71.88) v1(48.51,71.88)
  LAYER2 w0.381: v1(49.53,54.86) 49.53,56.39 48.26,57.66 48.26,64.77 v1(49.78,66.29) 49.78,71.5 49.4,71.88 v1(48.51,71.88)
  LAYER3 w0.254: v1(49.78,66.29) 43.2,66.29 42.69,65.79 v1(41.91,65.79)
3V3_ISO: length 123.3
  TOP w0.254: ADC1.19 19.49,43.04 19.49,44.45 19.23,44.7 v1(18.8,44.7) ; J7.1 15.49,5.84 v1(26.99,5.84) ; C29.1 20.75,88.39 v1(20.14,87.78) ; C97.1 17.39,34.8 v1(18.45,33.73) 18.54,33.64 R75.1
  TOP w0.635: C32.1 23.1,87.83 22.54,88.39 C29.1 21.59,96.77 PM1.6
  LAYER3 w0.254: v1(26.99,5.84) 26.99,6.62 v1(20.41,13.21)
  BOTTOM w0.254: v1(20.41,13.21) 20.96,13.76 20.96,31.22 v1(18.45,33.73) 18.45,43.52 18.8,43.87 v1(18.8,44.7) 18.8,46.23 20.32,47.75 20.32,62.74 19.54,63.52 19.54,79.88 19.49,79.93 19.49,87.13 v1(20.14,87.78)
5V: length 134.6
  TOP w0.254: C59.1 40.91,79.02 U20.1 39.01,79.63 38.72,79.34 33.6,79.34 33.52,79.25 ; 34.52,51.31 40.39,51.31 40.78,51.7 C74.1 41.83,52.58 41.83,53.45 40.8,54.48 U23.1 ; 34.52,51.31 33.52,52.31 ; 34.52,51.31 35.05,50.77 35.05,46.99 36.32,45.72 U24.1 40.17,45.03 40.78,44.42 C79.1 v1(45.97,43.69) ; 33.52,71.37 33.64,71.25 U21.1 40.17,70.62 40.78,70.01 C64.1 ; v1(45.97,34.8) 44.32,36.45 U25.1 40.17,35.78 40.78,35.17 C84.1
  TOP w0.381: C115.1 47.44,62.95 U32.1 46.42,61.66 46.23,61.47 42.3,61.47 41.54,60.71 C69.1 ; C69.1 39.76,61.72 33.52,61.72 ; C69.1 40.78,62.13 U22.1
  TOP w0.635: C55.1 31.75,88.26 v1(31.75,87.14) 32.14,86.74 C57.1 33.52,52.31
  LAYER2 w0.254: v1(45.97,34.8) v1(45.97,43.69)
  BOTTOM w0.635: v1(31.75,87.14) 31.75,96.9 PM3.6
5V_ISO: length 419.3
  TOP w0.254: U16.4 15.75,66.8 ; 15.75,66.8 15.75,69.54 14.97,70.32 C98.1 14.45,70.36 14.05,70.76 v1(14.05,71.88) ; 15.75,66.8 15.75,64.26 9.65,58.17 v1(9.65,56.84) 9.65,49.15 10.16,48.64 ; U25.8 31.62,36.45 31.75,36.58 ; 31.75,69.34 31.5,69.09 C65.1 30.37,69.13 29.43,70.07 U21.8 ; 31.75,77.72 31.62,77.6 C60.1 30.49,77.64 29.55,78.58 U20.8 ; U22.8 30.37,61.8 C70.1 31.75,60.71 ; U24.8 29.43,44.54 30.37,43.6 C80.1 31.62,43.56 31.75,43.43 ; U17.4 10.16,48.64 ; 10.16,48.64 9.91,48.39 9.91,41.66 10.47,41.09 11.04,41.09 ; 11.04,41.09 ADC1.5 ; 11.04,41.09 11.04,40.44 ; 31.75,52.83 31.5,52.58 C75.1 30.37,52.62 29.43,53.56 U23.8 ; 11.04,40.44 10.99,40.39 v1(9.65,40.39) 9.65,35.56 9.91,35.31 C96.1 ; 11.04,40.44 ADC1.6 ; v1(13.47,56.84) 14.47,55.84 C99.1
  TOP w0.381: v1(81.03,12.95) 80.76,12.69 C52.1 ; U30.8 52.45,49.91 51.56,50.8 ; C100.1 1.26,90.92 1.53,91.19 8.13,91.19 9.4,89.92 9.4,87.88 v1(11.94,85.34) ; C53.1 57.54,12.43 57.93,12.83 U7.8 59.18,11.93 v1(57.91,10.67) ; v1(73.15,51.05) 74.17,52.07 74.68,52.07 74.69,52.06 C109.1 75.95,50.17 76.2,49.91 U31.8
  TOP w0.635: C106.1 v1(51.56,49.02) 53.59,46.99 53.59,30.99 52.58,29.97 50.55,29.97 v1(44.83,24.26) ; C33.1 13.45,87.71 12.89,88.27 C28.1 ; v1(40.13,28.96) 33.53,28.96 30.37,32.12 C85.1 30.37,34.46 31.75,35.84 v1(31.75,83.91) ; C28.1 v1(11.94,85.34) ; C28.1 11.94,88.66 11.18,89.42 11.18,96.52 PM2.6 ; v1(81.03,12.95) 81.15,12.83 U6.8
  LAYER3 w0.254: v1(13.47,56.84) v1(9.65,56.84)
  LAYER3 w0.381: v1(57.91,10.67) 55.12,13.46 55.12,16.84
  LAYER3 w0.635: v1(11.94,85.34) 13.37,83.91 13.88,83.91 ; 13.88,83.91 14.05,83.74 v1(14.05,71.88) ; 13.88,83.91 v1(31.75,83.91) ; v1(40.13,28.96) v1(44.83,24.26) 45.21,23.88 45.21,16.84 ; 45.21,16.84 77.14,16.84 v1(81.03,12.95) ; 45.21,16.84 30.96,16.84 27.78,20.03 R74.3
  BOTTOM w0.254: 12.02,20.03 11.43,19.44 11.43,9.91 J7.2 ; 12.02,20.03 R74.3 ; 12.02,20.03 11.76,20.28 11.76,22.53 9.1,25.19 9.1,39.83 v1(9.65,40.39)
  BOTTOM w0.635: v1(51.56,49.02) 72.26,49.02 73.15,49.91 v1(73.15,51.05)
18V_GU: length 172.4
  TOP w0.635: v1(137.16,106.43) 137.16,105.43 135.23,103.5 U9.8 133.74,104.64 133.86,104.76 C37.1 ; PM4.6 41.91,97.03 C110.1 41.91,87.12 42.42,86.61 C111.1 ; v1(115.57,106.43) 112.65,103.5 U8.8 111.13,106.04 109.73,107.44 C36.1 ; U10.8 157.61,103.5 v1(160.53,106.43) C38.1
  LAYER2 w1.27: PM4.6 48.01,103.12 48.01,109.47 50.55,112.01 77.22,112.01 82.3,106.93 85.34,106.93 87.63,109.22 112.78,109.22 v1(115.57,106.43) v1(137.16,106.43) v1(160.53,106.43)
18V_IGBT1: length 59
  TOP w0.254: C24.1 58.04,78.73 59.44,77.33 59.44,74.42 62.74,71.12 84.58,71.12 86.36,69.34 86.36,67.31 87.12,66.55 88.14,66.55
  TOP w0.635: C39.1 88.14,65.78 U11.8 ; v1(59.94,89.41) 60.71,90.17 D13.1 ; C24.1 58.04,83.19 v1(59.94,85.09) 60.71,84.33 D8.1
  BOTTOM w0.635: v1(59.94,89.41) v1(59.94,85.09)
18V_IGBT2: length 42.7
  TOP w0.635: D14.1 59.44,92.46 v1(58.67,91.69) ; U15.8 64.14,67.44 C43.1 64.26,68.96 63.63,69.6 60.71,69.6 57.91,72.39 C25.1 56.9,76.2 56.39,76.71 56.39,85.09 v1(58.67,87.38) 59.44,86.61 D9.1
  BOTTOM w0.635: v1(58.67,87.38) v1(58.67,91.69)
18V_SCR2: length 48.9
  TOP w0.635: 93.22,84.58 94.49,84.58 98.04,88.14 101.09,88.14 103.12,90.17 111.39,90.17 113.03,88.53 C40.1 113.03,86.49 112.4,85.85 111.51,85.85 U12.8 ; 93.22,84.58 93.22,85.58 91.69,87.11 C21.1 91.69,88.85 89.74,90.81 D5.1 ; 93.22,84.58 91.69,83.06 87.63,83.06 87,83.69 D10.1
18V_SCR4: length 80.6
  TOP w0.635: v1(91.19,84.07) 89.03,86.23 D11.1 ; 134.1,85.47 U13.8 ; 134.1,85.47 135.38,86.75 C41.1 ; 134.1,85.47 135.23,85.47 135.61,85.85 v1(136.91,85.85) ; D6.1 90.3,93.09 v1(90.42,92.96) 91.69,91.69 C22.1
  LAYER2 w0.635: v1(136.91,85.85) 97.54,85.85 v1(90.42,92.96)
  LAYER3 w0.635: v1(91.19,84.07) 89.66,85.6 89.66,92.2 v1(90.42,92.96)
18V_SCR6: length 112.5
  TOP w0.635: 156.2,85.47 U14.8 ; 156.2,85.47 157.33,85.47 157.71,85.85 v1(160.53,85.85) ; 156.2,85.47 157.48,86.75 C42.1 ; D12.1 88.52,88.52 v1(91.19,85.85) ; D7.1 90.49,95.5 90.74,95.25 C23.1 90.93,96.01 v1(90.93,97.28)
  LAYER2 w0.635: v1(160.53,85.85) 156.46,89.92 98.3,89.92 v1(90.93,97.28) 88.65,95 88.65,88.39 v1(91.19,85.85)
GND: length 377.6
  TOP w0.254: R69.2 42.05,39.24 41.8,38.99 40.17,38.99 U25.4 ; U24.3 U24.4 ; U24.4 37.34,49.53 v1(37.08,49.78) ; U24.4 41.94,49.53 42.66,50.25 C78.2 42.77,50.18 R63.2 ; U23.4 40.17,59.73 39.23,60.67 C69.2 37.08,60.71 v1(37.03,60.76) ; C59.2 38.71,77.6 ; 38.71,77.6 38.71,75.89 39.54,75.06 U21.4 ; 38.71,77.6 37.08,77.6 v1(37.03,77.65) ; C64.2 39.23,68.11 40.17,67.17 U22.4 ; U22.4 41.43,66.55 41.94,67.06 C68.2 ; U22.4 U22.3 ; v1(37.03,57.38) 37.81,57.38 38.17,57.02 U23.3 41.74,57.02 42.91,55.85 C118.2 ; C79.2 37.8,43.69 v1(37.03,42.93) ; C74.2 38.47,52.58 38.2,52.31 v1(37.03,52.31) ; C63.2 41.81,75.44 41.43,75.06 U21.4 ; U25.4 41.53,40.26 42.04,40.77 C83.2 ; U25.4 38.48,40.26 38.1,39.88 38.1,34.67 38.35,34.42 C84.2 ; U22.3 v1(37.08,65.28) ; U22.3 40.8,65.28 41.34,64.74 41.71,64.74 43.17,63.28 C117.2 ; v1(37.02,82.3) 38.91,82.3 39.04,82.17 U20.3 U20.4 40.39,83.53 40.39,84.07 41.4,85.09 44.2,85.09 44.59,84.7 C58.2 44.61,83.93 R39.2 ; 82.04,76.86 80.77,75.59 C16.2 ; 82.04,76.86 U3.8 ; 82.04,76.86 U3.9 ; C116.2 43.17,71.92 41.68,73.41 41.68,73.53 41.43,73.79 U21.3 U21.4 ; C73.2 42.91,59.14 42.06,58.29 40.8,58.29 ; D15.2 79.5,23.38 79.23,23.11 78.99,23.11 v1(78.74,22.86) ; C20.1 93.98,78.49 R10.1 R13.2 ; D16.2 56.13,23.38 55.87,23.11 55.63,23.11 v1(55.37,22.86)
  TOP w0.381: J4.2 85.85,4.57 81.03,4.57 76.71,8.89 D17.1 ; D18.1 53.09,8.13 56.39,4.83 61.98,4.83 J5.2 ; v1(37.03,57.38) 37.95,58.29 U23.4 40.8,58.29 41.38,58.87 41.38,59.16 42.67,60.45 46.48,60.45 46.74,60.71 49.4,60.71 ; C114.2 49.03,59.67 49.4,60.04 49.4,60.71 ; 49.4,60.71 49.4,61.37 49.03,61.74 C115.2
  TOP w0.635: 2.03,105.55 2.03,106.3 2.67,106.93 3.42,106.93 ; C113.2 52.34,101.08 C112.2 52.32,102.62 v1(53.59,103.89) ; C20.1 94.73,78.5 95.25,77.98 95.25,75.95 93.47,74.17 C19.1 ; C54.2 2.03,97.54 1.27,96.77 1.27,96.44 1.26,96.43 C30.2 C31.2 C56.2 ; 80.77,72.14 87.88,72.14 88.02,72.28 C19.1 ; 80.77,72.14 C16.2 ; 80.77,72.14 76.13,72.14 ; C19.1 v1(88.02,75.3) ; v1(37.03,42.93) 38.3,41.66 39.62,41.66 40.17,41.11 U25.4 ; C57.2 35.06,88.51 C55.2 35.05,90.17 v1(35.56,90.68) ; C18.2 73.53,81.92 72.84,81.22 72.84,78.29 73.29,77.84 C17.2 75.04,77.09 R9.1 76.19,72.19 76.13,72.14 ; 76.13,72.14 v1(74.42,72.14) 72,72.14 70.1,74.03 R14.1
  TOP w1.27: J2.2 58.65,106.43 C5.2 53.82,111.25 PM4.1 PM3.1 PM1.1 PM2.1 9.65,111.25 5.59,107.19 3.67,107.19 2.03,105.55 C26.2 C27.2 C54.2
  BOTTOM w0.254: v1(37.08,49.78) 37.08,50.5 37.03,50.55 ; 37.03,65.79 37.08,65.74 v1(37.08,65.28)
  BOTTOM w0.635: v1(37.03,42.93) v1(37.03,52.31) v1(37.03,57.38) v1(37.03,60.76) v1(37.03,77.65) 37.03,78.62 37.02,78.63 v1(37.02,82.3) 37.02,89.22 v1(35.56,90.68) 35.56,93.85 PM3.7 35.31,97.92 35.31,109.35 PM3.1 ; v1(53.59,103.89) 55.6,105.89 C5.2
  vias: v1(56.9,22.86) v1(80.26,22.86) v1(127.51,75.44) v1(128.27,76.45) v1(128.27,74.42) v1(129.03,75.44) v1(129.79,76.45) v1(129.79,74.42) v1(130.56,75.44)
GND_SIGNAL: length 547.2
  TOP w0.254: R73.2 C89.2 44.84,27.78 41.7,24.64 D22.1 ; C102.1 12.7,28.7 12.18,29.22 U27.4 11.26,30.39 v1(10.92,30.73) ; U20.5 v1(29.55,85.51) ; C72.1 27.06,61.07 27.43,60.71 C70.2 28.82,60.08 28.96,59.94 v1(28.96,59.44) 29.21,59.18 29.21,58.51 U23.5 R55.1 ; 27.93,52.58 27.93,53.83 27.79,53.98 C77.1 ; 27.93,52.58 C75.2 ; 27.93,52.58 27.93,51.05 ; R61.1 27.93,49.53 ; 27.93,49.53 U24.5 ; 27.93,49.53 27.93,51.05 ; U11.3 77.34,60.33 75.95,58.93 v1(73.15,58.93) ; 27.55,43.56 26.94,44.18 C82.1 ; 27.55,43.56 28.19,44.2 v1(28.19,44.7) ; 27.55,43.56 C80.2 28.82,42.3 29.43,41.69 U25.5 R67.1 ; 27.46,68.33 27.71,68.07 v1(28.96,68.07) 29.43,67.6 U22.5 29.3,66.68 R49.1 ; 27.46,68.33 26.95,67.82 24.13,67.82 23.11,66.8 U16.11 17.27,66.8 16.52,67.55 C98.2 ; 27.46,68.33 27.46,69.09 ; R37.1 C62.1 26.94,77.61 26.92,77.6 ; 16.76,41.74 ADC1.4 ; 16.76,41.74 16.76,43.52 16.94,43.69 ; 16.76,41.74 ADC1.17 ; C97.2 19.63,35.31 20.14,34.8 v1(20.14,33.73) ; v1(14.48,39.88) 13.74,39.14 ADC1.8 ; C96.2 13.35,34.43 12.95,34.04 v1(11.94,34.04) ; 29.37,16.78 29.37,16.59 29.5,16.46 ; ADC1.20 16.94,43.69 ; 16.94,43.69 v1(16.76,43.87) ; C99.2 16.92,53.85 v1(18.45,52.31) 19.56,51.21 19.56,48.93 19.27,48.64 U17.11 ; 27.93,51.05 26.92,51.05 v1(26.67,50.8) ; U21.5 28.22,75.06 28.22,75.18 R43.1 27.06,76.34 v1(27.18,76.45) ; C65.2 27.46,69.09 ; 27.46,69.09 27.46,69.57 27.06,69.96 C67.1 ; v1(24.3,27.69) 23.89,28.09 C88.2 R71.2 ; C87.1 26.56,35.78 27.91,34.42 C85.2 28.82,33.41 28.96,33.27 v1(28.96,32) ; 26.92,77.6 24,77.6 v1(23.62,77.22) ; 26.92,77.6 C60.2
  TOP w0.381: J1.40 2.81,84.57 C100.2 ; v1(81.03,18.8) C50.2 83.05,17.34 83.05,17.33 83.05,16.64 80.03,16.64 79.76,16.37 C52.2 ; U15.3 56.9,59.94 57.91,58.93 57.91,56.39 56.13,54.6 U30.5 54.88,53.72 54.74,53.86 C105.2 C106.2 ; v1(57.66,18.29) C51.2 59.18,18.03 59.18,16.64 56.77,16.64 55.88,15.75 C53.2
  TOP w0.635: C33.2 15,88.25 C28.2 v1(14.99,90.42) ; C32.2 24.65,88.38 C29.2 25.65,88.39 26.29,89.03 v1(26.29,91.06) ; v1(145.16,80.39) 146.93,80.39 ; U9.3 v1(122.56,98.43) ; v1(30.73,14.99) 30.23,15.49 D23.1 29.5,16.65 29.37,16.78 D24.1 D25.1 D26.1 ; U10.3 v1(144.91,98.43) ; v1(48.39,53.72) 50.49,53.72 50.63,53.86 C106.2 ; v1(122.81,80.39) 124.84,80.39 ; v1(100.46,98.3) 100.58,98.43 U8.3 ; v1(100.33,80.52) 100.46,80.39 102.23,80.39 ; v1(40.64,13.72) 40.64,15.33 D19.1 40.8,17.26 40.67,17.39 D20.1 D21.1 D22.1 ; v1(73.15,52.58) 74.18,53.61 C109.2 C108.2 77.33,53.72 U31.5
  LAYER2 w0.254: v1(20.14,33.73) 20.14,33.85 19.86,34.13 19.86,44.7 ; J1.20 4.32,57.66 ; 27.06,44.7 v1(28.19,44.7) ; v1(16.76,43.87) 16.76,44.7
  LAYER2 w0.381: v1(81.03,18.8) 79.76,17.53 79.76,9.65 81.03,8.38 81.03,2.54 79.76,1.27 ; 57.19,1.31 57.19,1.49 56.39,2.29 56.39,13.39 56.38,13.4 56.38,14.03 56.39,14.04 56.39,17.02 v1(57.66,18.29)
  LAYER2 w0.635: 79.76,1.27 57.23,1.27 57.19,1.31 57.15,1.27 41.91,1.27 41.15,2.03
  LAYER2 w1.27: 32.26,81.03 33.47,79.81 71.18,79.81 73.66,82.3 84.84,82.3 86.61,80.52 v1(100.33,80.52) 111.25,80.52 112.15,81.42 116.96,81.42 117.86,80.52 121.39,80.52 121.52,80.39 v1(122.81,80.39) 135.51,80.39 136.41,81.29 139.69,81.29 140.72,80.26 143.74,80.26 143.87,80.39 v1(145.16,80.39) ; v1(144.91,98.43) 143.62,98.43 143.49,98.3 140.21,98.3 139.18,99.32 135.65,99.32 134.75,98.43 v1(122.56,98.43) 121.27,98.43 121.14,98.55 117.86,98.55 116.84,99.57 113.54,99.57 112.27,98.3 v1(100.46,98.3)
  LAYER3 w0.254: J7.10 16.47,15.03 R74.1
  LAYER3 w0.635: v1(32.77,51.05) 45.72,51.05 v1(48.39,53.72)
  BOTTOM w0.254: v1(73.15,58.93) v1(73.15,52.58)
  BOTTOM w0.635: v1(48.39,53.72) 52.2,49.9 70.48,49.9 v1(73.15,52.58)
  BOTTOM w1.27: v1(100.33,80.52) 100.33,81.81 100.46,81.93 v1(100.46,98.3)
VIN: length 178.2
  TOP w0.254: C16.1 77.72,75.44 76.96,76.2 76.96,78.05 76.19,78.83 R8.1 76.19,78.91 77.64,80.36 U3.1
  TOP w0.635: R8.1 75.67,79.39 C17.1 v1(74.29,80.52) ; v1(74.29,89.03) 74.29,93.09 72.72,94.66 TX1.1 ; C54.1 5.08,96.27 4.32,95.5 C30.1 C31.1 C56.1 ; PM4.2 49.28,102.87 C112.1 49.28,99.43 49.9,98.81 C113.1
  TOP w1.27: TX1.1 61.55,94.66 60.45,95.76 60.45,98.22 D1.1 60.53,101.04 C5.1 50.46,109.47 49.7,108.71 PM4.2 PM3.2 PM1.2 PM2.2 10.67,108.71 7.11,105.16 C26.1 C27.1 C54.1
  BOTTOM w0.635: v1(74.68,96.77) 74.68,95.8 74.29,95.42 v1(74.29,89.03) v1(74.29,80.52)
  BOTTOM w1.27: JP1.1 81.53,109.47 78.23,112.78 53.09,112.78 52.1,111.79 C5.1
ADC-VPOT-3V: length 49.3
  TOP w0.254: U17.13 17.16,49.94 16.76,50.34 v1(16.76,50.62) 16.8,50.59 U17.14
  BOTTOM w0.254: J1.38 5.33,79.5 17.02,79.5 19.11,77.41 19.11,62.94 19.81,62.23 19.81,51.58 18.85,50.62 v1(16.76,50.62)
ADC_DC-LINK: length 49
  TOP w0.254: R38.2 15.76,82.94 16.41,82.3 ; 16.41,82.3 C61.2 ; 16.41,82.3 v1(17.72,82.3) ; v1(14.97,69.1) 14.62,68.75 U16.1
  LAYER3 w0.254: v1(17.72,82.3) 17.72,76.9 14.97,74.16 v1(14.97,69.1)
  BOTTOM w0.254: v1(14.97,69.1) 14.19,69.1 13.95,69.34 5.89,69.34 5.33,68.78 5.33,65.02 6.1,64.26 7.4,64.26 8.38,63.28 8.38,53.38 7.84,52.83 J1.15
ADC_I_BUCK-1_3V: length 64.1
  TOP w0.254: v1(15.04,48.01) 16.35,46.69 U17.8 U17.9
  BOTTOM w0.254: v1(15.04,48.01) 15.04,45.26 14.48,44.7 13.46,44.7 13.02,45.14 13.02,54.95 14.26,56.18 14.26,60.93 17.27,63.95 17.27,70.1 12.95,74.42 3.3,74.42 2.54,75.18 2.54,81.28 3.3,82.04 5.33,82.04 J1.37
ADC_V_BUCK-1: length 55.6
  TOP w0.254: 18.29,60.2 v1(18.29,56.9) ; 18.29,60.2 18.29,60.96 17.27,61.98 R62.2 ; 18.29,60.2 17.65,60.83 C81.2 ; U17.1 12.57,58.29 v1(13.46,59.18)
  LAYER3 w0.254: v1(18.29,56.9) 16,59.18 v1(13.46,59.18)
  BOTTOM w0.254: v1(18.29,56.9) 18.29,57.68 18.54,57.92 18.54,76.82 17.13,78.23 J1.35
ADC_V_BUCK-2: length 50.6
  TOP w0.254: U17.7 13.33,46.69 13.73,46.29 v1(13.73,45.99) ; v1(16.52,57.15) C86.2 R68.2
  BOTTOM w0.254: J1.36 5.33,76.96 16.51,76.96 18.1,75.37 18.1,69.92 17.8,69.62 17.8,61.49 17.25,60.93 17.25,57.87 v1(16.52,57.15) 13.46,54.09 13.46,47.04 13.73,46.77 v1(13.73,45.99)
ADC_VA: length 118.6
  TOP w0.254: 16.41,79.25 16.41,78.49 13.36,78.49 12.19,77.32 v1(12.19,76.2) ; 16.41,79.25 16.41,80.39 R44.2 ; 16.41,79.25 C66.2 ; v1(16.51,39.37) 17.39,38.49 ADC1.12 ; U16.7 v1(10.41,64.85)
  LAYER2 w0.254: v1(35.31,55.12) 34.75,54.57 34.75,38.4 v1(35.31,37.85)
  LAYER3 w0.254: 9.24,66.64 12.19,69.59 v1(12.19,76.2) ; 9.24,66.64 9.08,66.8 2.96,66.8 2.03,65.87 2.03,54.86 J1.16 5.33,54.1 34.29,54.1 v1(35.31,55.12) ; 9.24,66.64 9.24,65.24 9.63,64.85 v1(10.41,64.85) ; v1(35.31,37.85) 34.75,37.29 18.59,37.29 v1(16.51,39.37)
ADC_VB: length 106
  TOP w0.254: 15.11,76.45 14.99,76.58 14.99,77.6 R50.2 ; 15.11,76.45 14.99,76.33 14.99,72.9 15.19,72.7 17.35,72.7 20.45,69.6 v1(22.1,69.6) ; 15.11,76.45 C71.2 ; v1(23.52,63.75) 22.42,64.85 U16.8 ; ADC1.11 17.02,37.84 16.76,38.1 v1(16.51,38.1)
  LAYER2 w0.254: v1(36.32,38.35) 35.23,39.45 35.23,53.07 36.11,53.96 36.11,55.84 v1(35.56,56.39)
  LAYER3 w0.254: 23.39,56.39 23.39,55.63 23.14,55.37 J1.17 ; 23.39,56.39 v1(35.56,56.39) ; 23.39,56.39 23.39,62.84 23.52,62.97 v1(23.52,63.75) ; v1(16.51,38.1) 17.78,36.83 36.07,36.83 36.32,37.08 v1(36.32,38.35)
  BOTTOM w0.254: v1(22.1,69.6) 22.1,67.95 23.52,66.53 v1(23.52,63.75)
ADC_VC: length 124.4
  TOP w0.254: ADC1.10 10.93,37.84 v1(10.67,38.1) ; U16.14 22.76,68.75 22.97,68.96 v1(23.75,68.96) 22.39,70.32 20.62,70.32 19.62,71.32 19.62,73.08 19.29,73.41 16.66,73.41 16.41,73.66 ; 16.41,73.66 16.41,74.8 R56.2 ; 16.41,73.66 C76.2
  LAYER2 w0.254: v1(35.56,67.82) 35.56,67.04 35.81,66.78 35.81,57.4 36.58,56.64 36.58,53.81 35.81,53.05 35.81,40.13 37.08,38.86 v1(37.08,37.34)
  LAYER3 w0.254: v1(37.08,37.34) 37.08,36.56 36.85,36.32 12.45,36.32 v1(10.67,38.1) ; v1(23.75,68.96) 22.1,67.31 22.1,62.23 21.08,61.21 21.08,56.9 20.07,55.88 16.26,55.88 14.26,57.87 8.85,57.87 7.62,56.64 5.33,56.64 J1.18
  BOTTOM w0.254: v1(35.56,67.82) 34.42,68.96 v1(23.75,68.96)
DC-LINK: length 122.9
  TOP w0.635: TP8.1 154.94,110.24 C38.2 152.91,106.43 152.15,105.66 152.15,97.28 153.54,95.89 U10.5 155.83,92.58 156.72,91.69 ; U8.5 107.57,95.89 105.66,97.79 C36.2 105.66,111.76 106.43,112.52 ; 135.13,91.95 133.74,93.34 U9.5 ; PM4.7 44.96,94.49 C110.2 44.97,88.38 C111.2 R33.1 ; 128.14,112.4 128.02,112.52
  LAYER3 w1.27: JP1.2 50.55,112.01 48.01,109.47 48.01,100.58 PM4.7
DSP_G1: length 107.1
  TOP w0.254: v1(73.66,64.26) R23.1
  LAYER2 w0.254: v1(76.96,35.31) 79.25,37.59 79.25,55.37 73.66,60.96 v1(73.66,64.26)
  LAYER3 w0.254: J1.1 9.14,32.51 17.53,32.51 18.03,33.02 50.04,33.02 50.62,33.6 75.26,33.6 v1(76.96,35.31)
DSP_G2: length 48.6
  TOP w0.254: v1(18.8,9.4) 18.03,10.16 3.56,10.16 1.84,11.88 1.84,28 4.57,30.73 4.57,33.31 4.06,33.82 J1.2
  BOTTOM w0.254: v1(18.8,9.4) 20.57,7.62 20.57,5.84 J7.7
DSP_G3: length 80
  TOP w0.254: v1(50.55,62.99) 51.31,63.75 R31.1
  LAYER2 w0.254: v1(50.55,62.99) 51.33,62.99 56.77,57.55 56.77,49.15 52.32,44.7 v1(52.32,36.83)
  LAYER3 w0.254: v1(52.32,36.83) 51.31,35.81 8.38,35.81 J1.3
DSP_G4: length 44
  TOP w0.254: J1.4 5.33,36.32 5.33,30.48 2.54,27.69 2.54,21.34 11.94,11.94 18.54,11.94 21.84,8.64 J7.8
DSP_G5: length 172.8
  TOP w0.254: v1(101.35,107.19) 99.82,107.19 98.55,105.92 R17.1
  LAYER3 w0.254: J1.5 8.13,40.13 9.14,41.15 20.13,41.15 21.66,39.62 95,39.62 96.27,40.89 v1(104.14,40.89)
  BOTTOM w0.254: v1(104.14,40.89) 105.41,42.16 105.41,103.12 v1(101.35,107.19)
DSP_G6: length 145
  TOP w0.254: v1(98.55,76.96) 98.55,78.74 96.77,80.52 96.77,84.6 98.16,85.98 R25.1
  LAYER3 w0.254: v1(98.55,39.06) 21.39,39.06 19.81,40.64 16.51,40.64 14.73,38.86 5.33,38.86 J1.6
  BOTTOM w0.254: v1(98.55,39.06) v1(98.55,76.96)
DSP_G7: length 179.6
  TOP w0.254: v1(118.62,104.14) R19.1
  LAYER3 w0.254: v1(120.65,44.2) 96.77,44.2 93.22,40.64 21.86,40.64 20.34,42.16 12.95,42.16 11.94,43.18 9.91,43.18 9.4,42.67 J1.7
  BOTTOM w0.254: v1(120.65,44.2) 120.65,102.11 v1(118.62,104.14)
DSP_G8: length 167.9
  TOP w0.254: v1(122.43,87.63) 121.16,86.36 R27.1
  LAYER3 w0.254: J1.8 5.33,41.4 8.38,41.4 8.64,41.66 20.24,41.66 21.76,40.13 93.73,40.13 96.52,42.93 v1(122.17,42.93)
  BOTTOM w0.254: v1(122.17,42.93) 122.17,78.23 121.67,78.74 121.67,86.87 v1(122.43,87.63)
DSP_G9: length 205
  TOP w0.254: v1(140.97,104.01) R21.1
  LAYER3 w0.254: v1(145.03,46.48) 144.53,46.99 97.54,46.99 92.2,41.66 22.35,41.66 20.83,43.18 18.8,43.18 17.41,44.57 10.04,44.57 9.4,45.21 J1.9
  BOTTOM w0.254: v1(145.03,46.48) 146.81,48.26 146.81,98.17 v1(140.97,104.01)
DSP_G10: length 187.3
  TOP w0.254: R29.1 143.26,86.89 143.74,87.38 v1(144.53,87.38)
  LAYER3 w0.254: v1(143.26,45.72) 97.28,45.72 92.71,41.15 22.1,41.15 20.57,42.67 15.75,42.67 14.48,43.94 5.33,43.94 J1.10
  BOTTOM w0.254: v1(144.53,87.38) 144.53,81.79 143.81,81.07 143.81,46.27 v1(143.26,45.72)
GPIO-20: length 71.3
  BOTTOM w0.254: J7.3 15.49,5.84 15.49,43.18 14.73,43.94 12.74,43.94 12.49,44.2 12.49,66.25 10.67,68.07 J1.27
GPIO-21: length 74
  TOP w0.254: v1(3.56,8.87) 15.01,8.87 J7.4
  BOTTOM w0.254: v1(3.56,8.87) 3.56,19.05 2.79,19.81 2.79,66.8 J1.28
GPIO-22: length 89.8
  TOP w0.254: J7.5 17.78,3.05 11.43,3.05 6.6,7.87 2.79,7.87 0.97,9.7 0.97,71.42 1.44,71.88 5.33,71.88 J1.29
GPIO-23: length 79.9
  TOP w0.254: J7.6 16.76,9.65 3.3,9.65 1.4,11.55 1.4,67.95 J1.30
I_BUCK-1: length 101.7
  TOP w0.254: ADC1.14 19.64,39.79 23.89,35.55 R70.1 29.46,31.24 v1(30.23,30.48)
  TOP w0.381: v1(81.28,14.48) 81.66,14.1 U6.7
  LAYER2 w0.254: v1(76.2,30.48) 79.76,30.48 82.24,28 82.24,15.44 v1(81.28,14.48) ; TP1.1 v1(79.76,7.11)
  LAYER3 w0.254: v1(30.23,30.48) v1(76.2,30.48)
  BOTTOM w0.381: v1(79.76,7.11) 79.76,13.97 80.26,14.48 v1(81.28,14.48)
I_BUCK-2: length 91.6
  TOP w0.254: v1(22.86,34.04) 22.31,34.59 22.31,36.37 19.53,39.14 ADC1.13
  TOP w0.381: U7.7 57.53,14.1 v1(57.15,13.72)
  LAYER2 w0.254: TP2.1 54.31,5.29 54.31,36.53 v1(54.86,37.08)
  LAYER3 w0.254: v1(54.86,37.08) 52.32,34.54 50.55,34.54 49.78,33.78 23.9,33.78 23.64,34.04 v1(22.86,34.04)
  BOTTOM w0.381: v1(57.15,13.72) 55.88,12.45 55.88,6.86 TP2.1
I_L4: length 69.6
  TOP w0.254: ADC1.16 21.03,41.09 22.1,42.16 v1(22.1,43.69) ; U31.7 77.34,51.18 v1(76.96,50.8)
  LAYER2 w0.254: v1(76.96,50.8) 76.96,47.5 TP3.1
  LAYER3 w0.254: TP3.1 56.39,43.18 54.36,45.21 45.47,45.21 43.94,43.69 v1(22.1,43.69)
I_L5: length 46.1
  TOP w0.254: v1(53.34,50.8) 53.72,51.18 U30.7 ; ADC1.15 22.41,40.44 22.86,40.89 v1(22.86,42.67)
  LAYER2 w0.254: v1(53.34,50.8) 53.34,47.24 TP4.1
  LAYER3 w0.254: v1(22.86,42.67) 23.41,42.12 45.93,42.12 46.99,43.18 TP4.1
IGBT_G1: length 6.7
  TOP w0.635: R24.2 93.73,59.44 Q1.1
IGBT_G2: length 6.9
  TOP w0.635: R32.2 70.1,58.93 Q2.1
IGBT_S1: length 78.4
  TOP w0.635: 62.36,79.88 62.36,79.88 C24.2 ; 62.36,79.88 62.36,75.82 v1(64.26,73.91) ; 62.36,79.88 v1(62.36,81.15) ; v1(83.31,58.42) 83.95,57.79 U11.5 87.64,57.66 85.6,57.66 85.09,58.17 C39.2 83.31,67.82 v1(82.55,68.58) ; v1(70.1,90.17) 69.61,90.66 TX1.3 65.94,90.66 D13.2
  LAYER2 w0.635: Q1.3 88.9,52.83 v1(83.31,58.42)
  BOTTOM w0.635: v1(82.55,68.58) 69.6,68.58 v1(64.26,73.91) ; v1(62.36,81.15) 70.1,88.9 v1(70.1,90.17)
IGBT_S2: length 62.7
  TOP w0.381: 66.8,56.24 66.8,56.39 65.79,57.4 65.64,57.4
  TOP w0.635: v1(61.47,73.91) 60.96,74.42 C25.2 ; v1(71.37,91.95) 70.66,92.66 TX1.2 65.66,92.66 D14.2 ; v1(58.93,68.58) 59.94,67.56 C43.2 61.21,58.67 62.48,57.4 U15.5 65.64,57.4 66.8,56.24 66.8,53.09 67.31,52.58 Q2.3
  BOTTOM w0.635: v1(58.93,68.58) 58.93,71.37 v1(61.47,73.91) 71.37,83.82 v1(71.37,91.95)
LED1: length 57.1
  TOP w0.254: R80.1 32,15.49 30.67,16.83 v1(30.67,22.25) ; J1.11 7.87,46.48 7.87,24.96 v1(10.59,22.25)
  LAYER3 w0.254: v1(30.67,22.25) v1(10.59,22.25)
LED2: length 58.8
  TOP w0.254: J1.12 2.83,47.75 2.29,47.21 2.29,33.27 v1(3.56,32) ; R81.1 v1(33.16,18.54)
  LAYER3 w0.254: v1(33.16,18.54) 33.71,19.09 33.71,25.21 26.92,32 v1(3.56,32)
LED3: length 61.1
  TOP w0.254: R82.1 v1(32.26,21.59)
  LAYER3 w0.254: v1(32.26,21.59) 32.26,25.34 27.88,29.72 3.56,29.72 2.03,31.24 2.03,48.51 2.54,49.02 5.33,49.02 J1.13
LED4: length 57.7
  TOP w0.254: R83.1 v1(30.85,24.64)
  LAYER3 w0.254: v1(30.85,24.64) 26.52,28.97 2.27,28.97 1.52,29.72 1.52,49.72 2.09,50.29 J1.14
LED5: length 65.9
  TOP w0.254: R84.1 21.24,15.49 8.38,28.35 8.38,71.37 J1.31
LED6: length 76.3
  TOP w0.254: R85.1 v1(21.84,18.54)
  LAYER3 w0.254: v1(2.54,18.8) 20.81,18.8 21.06,18.54 v1(21.84,18.54)
  BOTTOM w0.254: J1.32 1.99,71.08 1.99,19.35 v1(2.54,18.8)
LED7: length 64.3
  TOP w0.254: J1.33 8.89,73.41 8.89,30.48 17.78,21.59 R86.1
LED8: length 74.5
  TOP w0.254: R87.1 20.07,24.64 v1(19.3,23.88)
  LAYER3 w0.254: J1.34 1.05,72.68 1.05,25.81 1.31,25.55 17.63,25.55 v1(19.3,23.88)
SCR_G1: length 4.1
  TOP w0.635: R88.2 115.09,98.48 115.06,98.45 SCR1.3
SCR_G2: length 4.1
  TOP w0.635: R89.2 115.09,80.45 115.06,80.42 SCR2.3
SCR_G3: length 4.1
  TOP w0.635: SCR3.3 137.92,98.45 137.95,98.48 R90.2
SCR_G4: length 4.1
  TOP w0.635: SCR4.3 137.92,80.42 137.95,80.45 R91.2
SCR_G5: length 4.1
  TOP w0.635: R92.2 159.8,98.48 159.77,98.45 SCR5.3
SCR_G6: length 4.1
  TOP w0.635: R93.2 160.05,80.45 160.02,80.42 SCR6.3
SPI_CS: length 28.9
  TOP w0.254: ADC1.3 v1(10.83,42.39)
  BOTTOM w0.254: J1.26 5.33,64.26 5.33,47.24 6.1,46.48 8.13,46.48 10.83,43.78 v1(10.83,42.39)
SPI_DIN: length 27.8
  TOP w0.254: ADC1.2 v1(13.82,43.04)
  LAYER3 w0.254: J1.23 v1(11.78,62.99)
  BOTTOM w0.254: v1(13.82,43.04) 12.73,43.04 11.94,43.83 11.94,62.84 v1(11.78,62.99)
SPI_DOUT: length 41.8
  TOP w0.254: ADC1.18 19.94,42.39 20.57,43.02 v1(20.57,44.45)
  LAYER3 w0.254: v1(21.08,64.01) 20.3,64.01 20.05,63.75 8.89,63.75 8.38,64.26 5.33,64.26 J1.24
  BOTTOM w0.254: v1(21.08,64.01) 21.08,45.74 20.57,45.23 v1(20.57,44.45)
SPI_SCLK: length 25.6
  TOP w0.254: v1(11.08,45.36) 11.08,44.29 11.68,43.69 ADC1.1
  BOTTOM w0.254: v1(11.08,45.36) 10.53,45.91 10.53,62.84 7.84,65.53 J1.25
V_BUCK-1: length 57.3
  TOP w0.254: TP9.1 94.74,4.83 93.22,6.35
  TOP w0.635: R58.1 R15.1 80.11,20.17 84.07,24.13 C4.1
  TOP w1.27: U6.1 90.34,12.83 90.72,13.21 90.97,12.95 91.95,12.95 93.22,11.68 93.22,6.35 88.9,2.03 81.53,2.03 74.93,8.64 JP5.1
V_BUCK-2: length 35.3
  TOP w0.254: JP5.2 69.6,8.64 69.6,3.81 70.36,3.05 TP10.1
  TOP w0.635: C35.1 60.96,24.13 57.25,20.42 R16.1 R64.1
  TOP w1.27: JP5.2 70.48,12.83 U7.1
VA: length 27
  TOP w0.254: R40.1 123.44,8.13 123.7,8.38 J3.1 125.73,7.37
  BOTTOM w0.254: J3.1 126.75,11.18 127.51,11.94 TP5.1
VB: length 25.7
  TOP w0.254: R46.1 129.29,5.84 J3.2
  BOTTOM w0.254: TP6.1 143.51,10.41 132.53,10.41 131.83,9.71 J3.2
VC: length 25.4
  TOP w0.254: J3.3 132.08,3.56 R52.1
  BOTTOM w0.254: TP7.1 139.45,5.84 J3.3
VMID1: length 91.2
  TOP w0.254: 81.54,84.66 81.76,84.66 82.51,83.92 D10.2
  TOP w0.635: C40.2 108.71,88.14 107.95,87.38 107.95,78.99 109.09,77.85 U12.5 111.13,74.54 111.76,73.91 SCR2.1 ; D10.2 81.54,84.66 TX1.7 v1(76.71,84.66) ; SCR1.2 113.64,94.49 112.88,93.73 104.14,93.73 99.66,89.25 v1(97.44,89.25) 95.69,87.5 C21.2
  LAYER3 w0.635: v1(76.71,84.66) 78.23,86.19 78.23,93.22 84.58,99.57 92.46,99.57 96.75,95.27 96.75,89.94 v1(97.44,89.25)
VMID2: length 115.9
  TOP w0.635: U13.5 131.95,77.85 130.44,79.36 130.44,87.2 131.38,88.14 ; D11.2 82.08,86.66 TX1.8 77.59,86.66 77.39,86.87 77.36,86.87 v1(77.1,87.12) ; 131.38,88.14 v1(125.22,88.14) ; 131.38,88.14 C41.2 ; C22.2 v1(99.06,91.44)
  LAYER3 w0.635: v1(77.1,87.12) 77.1,93.61 84.07,100.58 92.96,100.58 99.1,94.45 ; 125.22,92.71 127,94.49 SCR3.2 ; 125.22,92.71 v1(125.22,88.14) ; 125.22,92.71 118.87,99.06 103.63,99.06 99.1,94.53 99.1,94.45 ; 99.1,94.45 99.1,91.48 v1(99.06,91.44)
VMID3: length 130.9
  TOP w0.635: D12.2 82.36,88.66 TX1.9 77.2,88.66 v1(75.95,89.92) ; 153.48,88.14 152.97,88.65 v1(151.38,88.65) ; 153.48,88.14 C42.2 ; 153.48,88.14 153.16,88.14 152.65,87.63 152.65,79.12 153.92,77.85 U14.5 ; v1(96.77,100.08) 96.77,96.27 95.76,95.25 C23.2
  LAYER3 w0.635: v1(151.38,88.65) 151.38,91.69 154.18,94.49 ; 154.18,94.49 148.59,100.08 v1(96.77,100.08) 95,100.08 93.47,101.6 83.57,101.6 75.95,93.98 v1(75.95,89.92) ; 154.18,94.49 SCR5.2
VPOT: length 67.2
  TOP w0.254: v1(43.97,35) 44.84,34.13 R72.1 ; ADC1.9 14.09,38.49 14.48,38.1 14.48,34.54 13.21,33.27 v1(10.16,33.27)
  LAYER3 w0.254: v1(43.97,35) 43.19,35 43.02,35.17 16.61,35.17 14.71,33.27 v1(10.16,33.27)
  BOTTOM w0.254: v1(10.16,33.27) 10.16,25.65 14.55,21.26 14.55,18.96 R74.2
N07970: length 3.8
  TOP w0.254: U3.3 78.23,79.36 R8.2 R9.2
N08403: length 5.3
  TOP w0.254: U3.5 80.34,78.36 80.77,78.8 80.77,81.66 80.52,81.92 C18.1
N08410: length 2.5
  TOP w0.254: U3.12 85.65,78.36 85.78,78.49 R10.2
N08443: length 4.7
  TOP w0.254: U3.10 84.74,77.36 86.47,75.63 C19.2
